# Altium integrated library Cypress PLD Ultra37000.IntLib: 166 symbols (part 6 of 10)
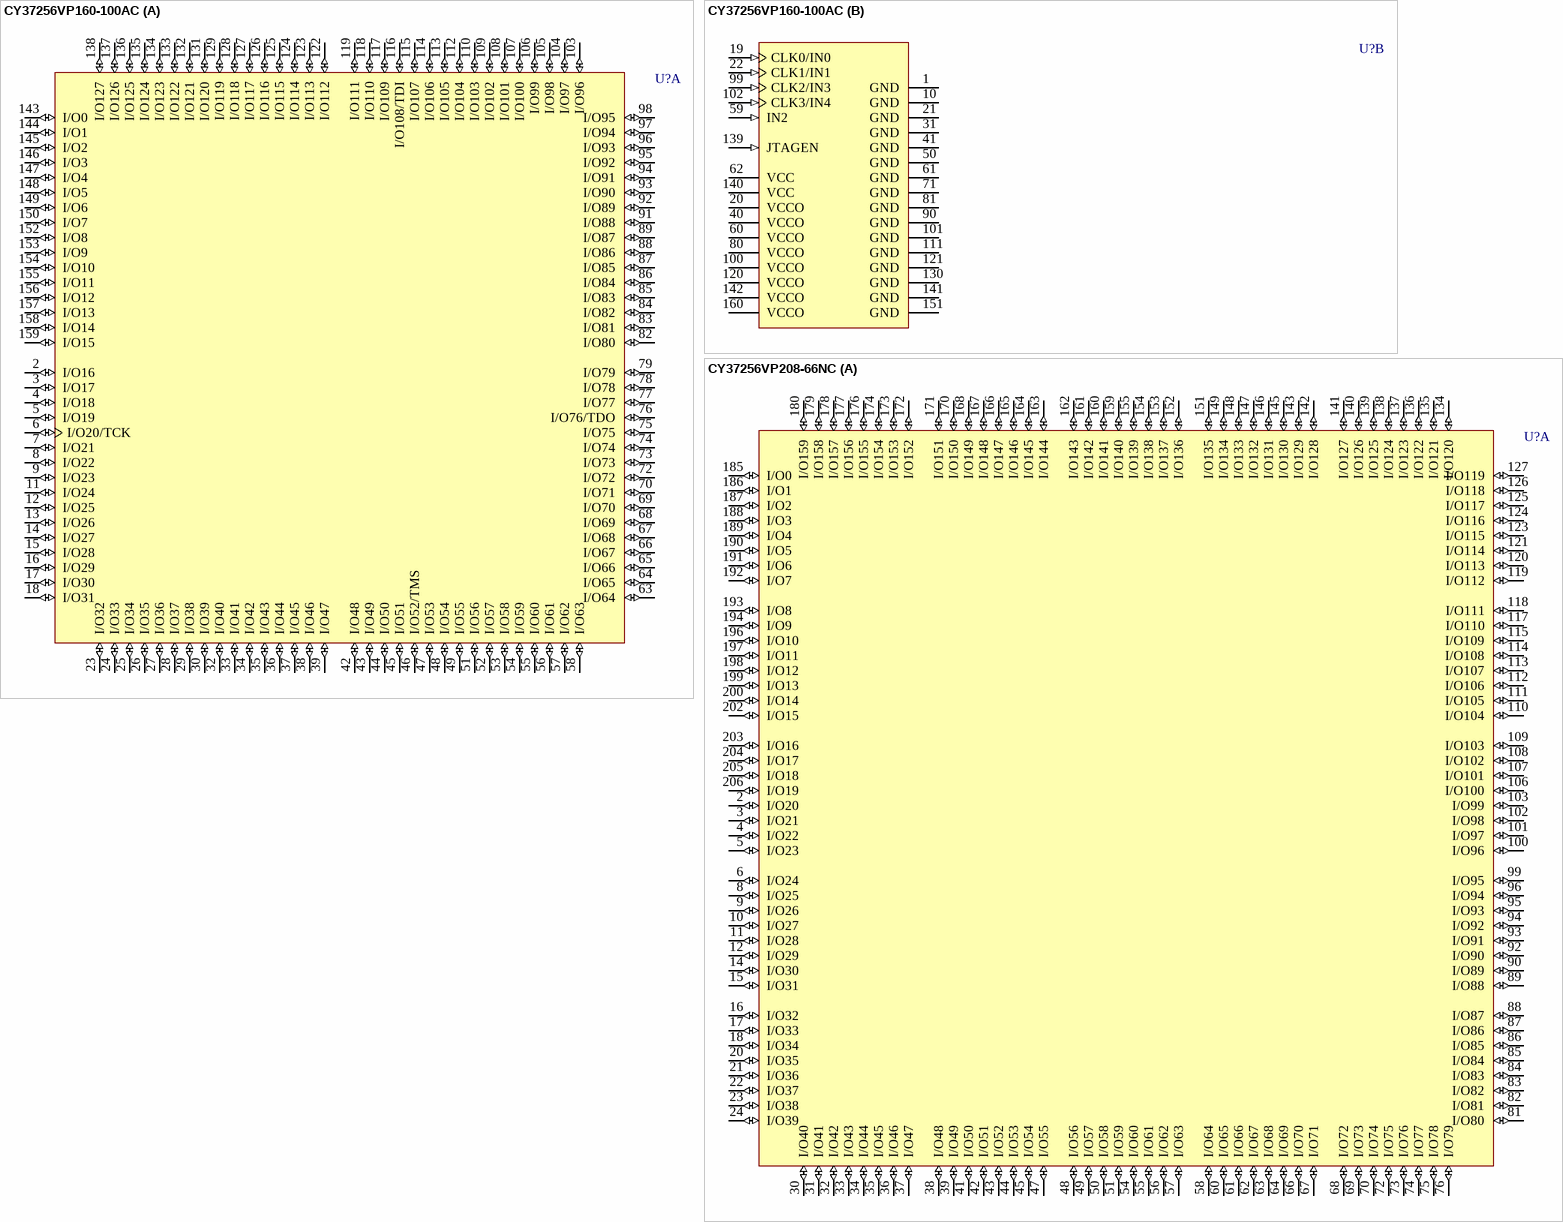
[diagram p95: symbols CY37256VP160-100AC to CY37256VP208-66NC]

## CY37256VP160-100AC
designator U?
Ultra37000 3.3V, ISR High-Performance CPLD
footprint A160_N (Thin QFP, 160-Leads, Body 24x24mm, Pitch 0.5mm, IPC Medium Density)
footprint A160_L (Thin QFP, 160-Leads, Body 24x24mm, Pitch 0.5mm, IPC High Density)
footprint A160_M (Thin QFP, 160-Leads, Body 24x24mm, Pitch 0.5mm, IPC Low Density)
3D model CY37256VP160-A160 (160-Pin Thin Quad Flat Pack 0.5 mm Pitch)
part A pins: 2 I/O16 (io), 3 I/O17 (io), 4 I/O18 (io), 5 I/O19 (io), 6 I/O20/TCK (io), 7 I/O21 (io), 8 I/O22 (io), 9 I/O23 (io), 11 I/O24 (io), 12 I/O25 (io), 13 I/O26 (io), 14 I/O27 (io), 15 I/O28 (io), 16 I/O29 (io), 17 I/O30 (io), 18 I/O31 (io), 23 I/O32 (io), 24 I/O33 (io), 25 I/O34 (io), 26 I/O35 (io), 27 I/O36 (io), 28 I/O37 (io), 29 I/O38 (io), 30 I/O39 (io), 32 I/O40 (io), 33 I/O41 (io), 34 I/O42 (io), 35 I/O43 (io), 36 I/O44 (io), 37 I/O45 (io), 38 I/O46 (io), 39 I/O47 (io), 42 I/O48 (io), 43 I/O49 (io), 44 I/O50 (io), 45 I/O51 (io), 46 I/O52/TMS (io), 47 I/O53 (io), 48 I/O54 (io), 49 I/O55 (io), 51 I/O56 (io), 52 I/O57 (io), 53 I/O58 (io), 54 I/O59 (io), 55 I/O60 (io), 56 I/O61 (io), 57 I/O62 (io), 58 I/O63 (io), 63 I/O64 (io), 64 I/O65 (io), 65 I/O66 (io), 66 I/O67 (io), 67 I/O68 (io), 68 I/O69 (io), 69 I/O70 (io), 70 I/O71 (io), 72 I/O72 (io), 73 I/O73 (io), 74 I/O74 (io), 75 I/O75 (io), 76 I/O76/TDO (io), 77 I/O77 (io), 78 I/O78 (io), 79 I/O79 (io), 82 I/O80 (io), 83 I/O81 (io), 84 I/O82 (io), 85 I/O83 (io), 86 I/O84 (io), 87 I/O85 (io), 88 I/O86 (io), 89 I/O87 (io), 91 I/O88 (io), 92 I/O89 (io), 93 I/O90 (io), 94 I/O91 (io), 95 I/O92 (io), 96 I/O93 (io), 97 I/O94 (io), 98 I/O95 (io), 103 I/O96 (io), 104 I/O97 (io), 105 I/O98 (io), 106 I/O99 (io), 107 I/O100 (io), 108 I/O101 (io), 109 I/O102 (io), 110 I/O103 (io), 112 I/O104 (io), 113 I/O105 (io), 114 I/O106 (io), 115 I/O107 (io), 116 I/O108/TDI (io), 117 I/O109 (io), 118 I/O110 (io), 119 I/O111 (io), 122 I/O112 (io), 123 I/O113 (io), 124 I/O114 (io), 125 I/O115 (io), 126 I/O116 (io), 127 I/O117 (io), 128 I/O118 (io), 129 I/O119 (io), 131 I/O120 (io), 132 I/O121 (io), 133 I/O122 (io), 134 I/O123 (io), 135 I/O124 (io), 136 I/O125 (io), 137 I/O126 (io), 138 I/O127 (io), 143 I/O0 (io), 144 I/O1 (io), 145 I/O2 (io), 146 I/O3 (io), 147 I/O4 (io), 148 I/O5 (io), 149 I/O6 (io), 150 I/O7 (io), 152 I/O8 (io), 153 I/O9 (io), 154 I/O10 (io), 155 I/O11 (io), 156 I/O12 (io), 157 I/O13 (io), 158 I/O14 (io), 159 I/O15 (io)
part B pins: 1 GND (power), 10 GND (power), 19 CLK0/IN0 (in), 20 VCCO (power), 21 GND (power), 22 CLK1/IN1 (in), 31 GND (power), 40 VCCO (power), 41 GND (power), 50 GND (power), 59 IN2 (in), 60 VCCO (power), 61 GND (power), 62 VCC (power), 71 GND (power), 80 VCCO (power), 81 GND (power), 90 GND (power), 99 CLK2/IN3 (in), 100 VCCO (power), 101 GND (power), 102 CLK3/IN4 (in), 111 GND (power), 120 VCCO (power), 121 GND (power), 130 GND (power), 139 JTAGEN (in), 140 VCC (power), 141 GND (power), 142 VCCO (power), 151 GND (power), 160 VCCO (power)

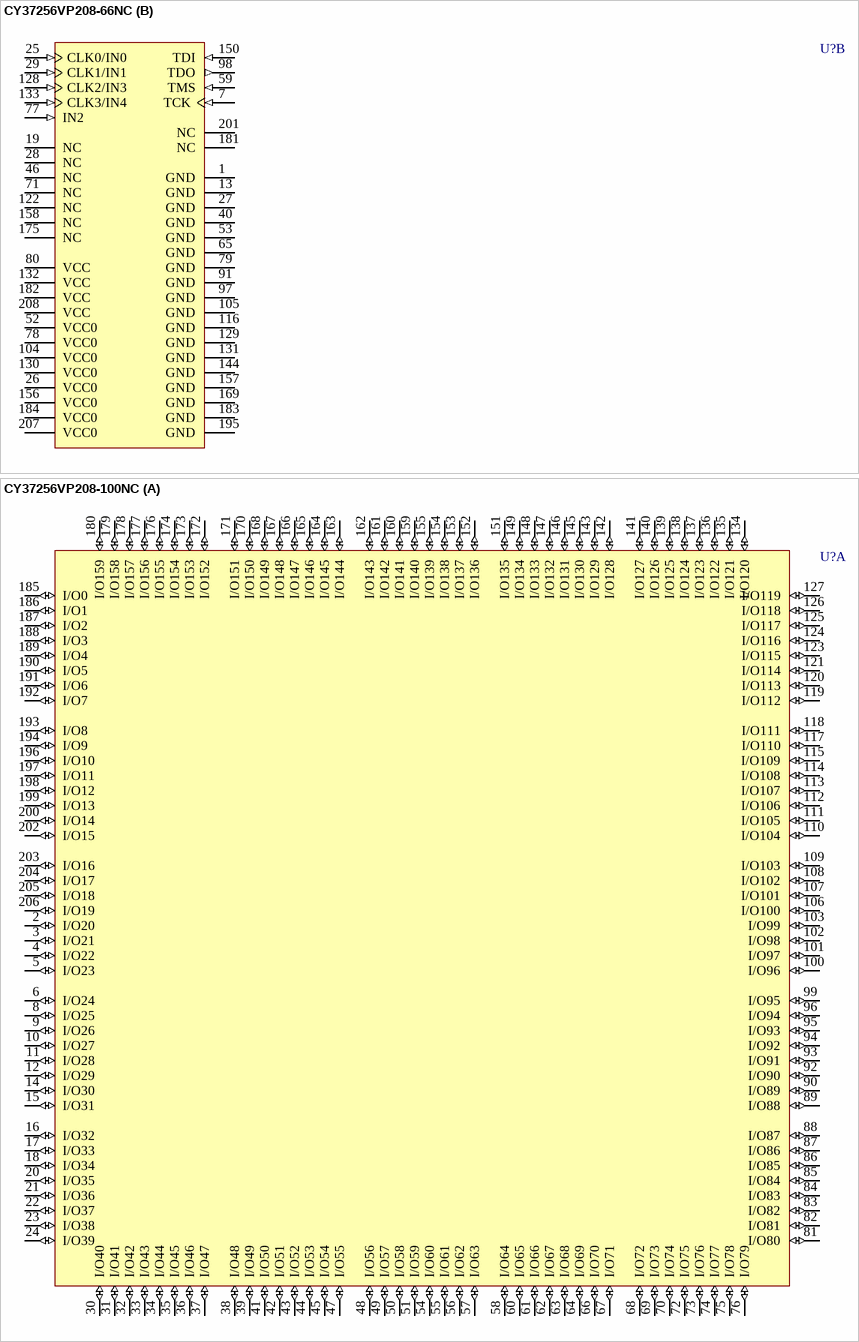
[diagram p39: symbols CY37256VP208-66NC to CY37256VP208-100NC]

## CY37256VP208-66NC
designator U?
Ultra37000 3.3V, ISR High-Performance CPLD
footprint N208_N (Shrink QFP, 208-Leads, Body 28x28mm, Pitch 0.5mm, IPC Medium Density)
footprint N208_L (Shrink QFP, 208-Leads, Body 28x28mm, Pitch 0.5mm, IPC High Density)
footprint N208_M (Shrink QFP, 208-Leads, Body 28x28mm, Pitch 0.5mm, IPC Low Density)
3D model CY37256VP208-N208 (208-Pin Plastic Shrink Quad Flat Pack 0.5 mm Pitch)
part A pins: 2 I/O20 (io), 3 I/O21 (io), 4 I/O22 (io), 5 I/O23 (io), 6 I/O24 (io), 8 I/O25 (io), 9 I/O26 (io), 10 I/O27 (io), 11 I/O28 (io), 12 I/O29 (io), 14 I/O30 (io), 15 I/O31 (io), 16 I/O32 (io), 17 I/O33 (io), 18 I/O34 (io), 20 I/O35 (io), 21 I/O36 (io), 22 I/O37 (io), 23 I/O38 (io), 24 I/O39 (io), 30 I/O40 (io), 31 I/O41 (io), 32 I/O42 (io), 33 I/O43 (io), 34 I/O44 (io), 35 I/O45 (io), 36 I/O46 (io), 37 I/O47 (io), 38 I/O48 (io), 39 I/O49 (io), 41 I/O50 (io), 42 I/O51 (io), 43 I/O52 (io), 44 I/O53 (io), 45 I/O54 (io), 47 I/O55 (io), 48 I/O56 (io), 49 I/O57 (io), 50 I/O58 (io), 51 I/O59 (io), 54 I/O60 (io), 55 I/O61 (io), 56 I/O62 (io), 57 I/O63 (io), 58 I/O64 (io), 60 I/O65 (io), 61 I/O66 (io), 62 I/O67 (io), 63 I/O68 (io), 64 I/O69 (io), 66 I/O70 (io), 67 I/O71 (io), 68 I/O72 (io), 69 I/O73 (io), 70 I/O74 (io), 72 I/O75 (io), 73 I/O76 (io), 74 I/O77 (io), 75 I/O78 (io), 76 I/O79 (io), 81 I/O80 (io), 82 I/O81 (io), 83 I/O82 (io), 84 I/O83 (io), 85 I/O84 (io), 86 I/O85 (io), 87 I/O86 (io), 88 I/O87 (io), 89 I/O88 (io), 90 I/O89 (io), 92 I/O90 (io), 93 I/O91 (io), 94 I/O92 (io), 95 I/O93 (io), 96 I/O94 (io), 99 I/O95 (io), 100 I/O96 (io), 101 I/O97 (io), 102 I/O98 (io), 103 I/O99 (io), 106 I/O100 (io), 107 I/O101 (io), 108 I/O102 (io), 109 I/O103 (io), 110 I/O104 (io), 111 I/O105 (io), 112 I/O106 (io), 113 I/O107 (io), 114 I/O108 (io), 115 I/O109 (io), 117 I/O110 (io), 118 I/O111 (io), 119 I/O112 (io), 120 I/O113 (io), 121 I/O114 (io), 123 I/O115 (io), 124 I/O116 (io), 125 I/O117 (io), 126 I/O118 (io), 127 I/O119 (io), 134 I/O120 (io), 135 I/O121 (io), 136 I/O122 (io), 137 I/O123 (io), 138 I/O124 (io), 139 I/O125 (io), 140 I/O126 (io), 141 I/O127 (io), 142 I/O128 (io), 143 I/O129 (io), 145 I/O130 (io), 146 I/O131 (io), 147 I/O132 (io), 148 I/O133 (io), 149 I/O134 (io), 151 I/O135 (io), 152 I/O136 (io), 153 I/O137 (io), 154 I/O138 (io), 155 I/O139 (io), 159 I/O140 (io), 160 I/O141 (io), 161 I/O142 (io), 162 I/O143 (io), 163 I/O144 (io), 164 I/O145 (io), 165 I/O146 (io), 166 I/O147 (io), 167 I/O148 (io), 168 I/O149 (io), 170 I/O150 (io), 171 I/O151 (io), 172 I/O152 (io), 173 I/O153 (io), 174 I/O154 (io), 176 I/O155 (io), 177 I/O156 (io), 178 I/O157 (io), 179 I/O158 (io), 180 I/O159 (io), 185 I/O0 (io), 186 I/O1 (io), 187 I/O2 (io), 188 I/O3 (io), 189 I/O4 (io), 190 I/O5 (io), 191 I/O6 (io), 192 I/O7 (io), 193 I/O8 (io), 194 I/O9 (io), 196 I/O10 (io), 197 I/O11 (io), 198 I/O12 (io), 199 I/O13 (io), 200 I/O14 (io), 202 I/O15 (io), 203 I/O16 (io), 204 I/O17 (io), 205 I/O18 (io), 206 I/O19 (io)
part B pins: 1 GND (power), 7 TCK (in), 13 GND (power), 19 NC, 25 CLK0/IN0 (in), 26 VCC0 (power), 27 GND (power), 28 NC, 29 CLK1/IN1 (in), 40 GND (power), 46 NC, 52 VCC0 (power), 53 GND (power), 59 TMS (in), 65 GND (power), 71 NC, 77 IN2 (in), 78 VCC0 (power), 79 GND (power), 80 VCC (power), 91 GND (power), 97 GND (power), 98 TDO (out), 104 VCC0 (power), 105 GND (power), 116 GND (power), 122 NC, 128 CLK2/IN3 (in), 129 GND (power), 130 VCC0 (power), 131 GND (power), 132 VCC (power), 133 CLK3/IN4 (in), 144 GND (power), 150 TDI (in), 156 VCC0 (power), 157 GND (power), 158 NC, 169 GND (power), 175 NC, 181 NC, 182 VCC (power), 183 GND (power), 184 VCC0 (power), 195 GND (power), 201 NC, 207 VCC0 (power), 208 VCC (power)

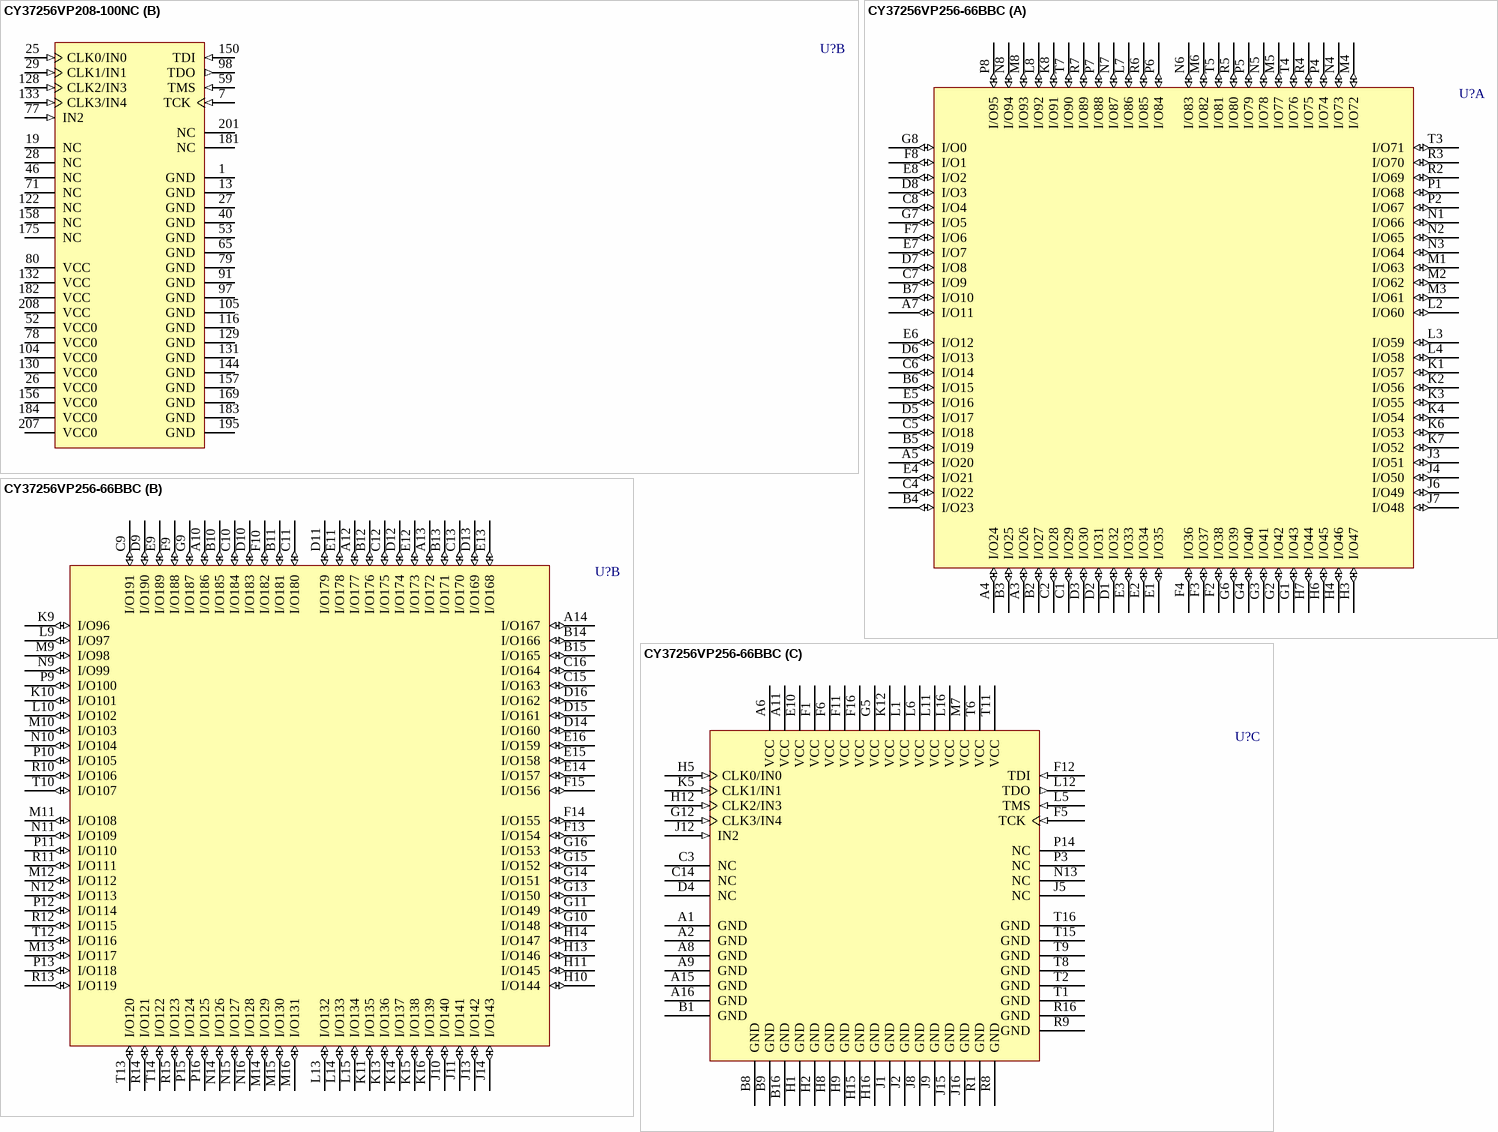
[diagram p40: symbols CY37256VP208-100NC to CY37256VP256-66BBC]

## CY37256VP208-100NC
designator U?
Ultra37000 3.3V, ISR High-Performance CPLD
footprint N208_N (Shrink QFP, 208-Leads, Body 28x28mm, Pitch 0.5mm, IPC Medium Density)
footprint N208_L (Shrink QFP, 208-Leads, Body 28x28mm, Pitch 0.5mm, IPC High Density)
footprint N208_M (Shrink QFP, 208-Leads, Body 28x28mm, Pitch 0.5mm, IPC Low Density)
3D model CY37256VP208-N208 (208-Pin Plastic Shrink Quad Flat Pack 0.5 mm Pitch)
part A pins: 2 I/O20 (io), 3 I/O21 (io), 4 I/O22 (io), 5 I/O23 (io), 6 I/O24 (io), 8 I/O25 (io), 9 I/O26 (io), 10 I/O27 (io), 11 I/O28 (io), 12 I/O29 (io), 14 I/O30 (io), 15 I/O31 (io), 16 I/O32 (io), 17 I/O33 (io), 18 I/O34 (io), 20 I/O35 (io), 21 I/O36 (io), 22 I/O37 (io), 23 I/O38 (io), 24 I/O39 (io), 30 I/O40 (io), 31 I/O41 (io), 32 I/O42 (io), 33 I/O43 (io), 34 I/O44 (io), 35 I/O45 (io), 36 I/O46 (io), 37 I/O47 (io), 38 I/O48 (io), 39 I/O49 (io), 41 I/O50 (io), 42 I/O51 (io), 43 I/O52 (io), 44 I/O53 (io), 45 I/O54 (io), 47 I/O55 (io), 48 I/O56 (io), 49 I/O57 (io), 50 I/O58 (io), 51 I/O59 (io), 54 I/O60 (io), 55 I/O61 (io), 56 I/O62 (io), 57 I/O63 (io), 58 I/O64 (io), 60 I/O65 (io), 61 I/O66 (io), 62 I/O67 (io), 63 I/O68 (io), 64 I/O69 (io), 66 I/O70 (io), 67 I/O71 (io), 68 I/O72 (io), 69 I/O73 (io), 70 I/O74 (io), 72 I/O75 (io), 73 I/O76 (io), 74 I/O77 (io), 75 I/O78 (io), 76 I/O79 (io), 81 I/O80 (io), 82 I/O81 (io), 83 I/O82 (io), 84 I/O83 (io), 85 I/O84 (io), 86 I/O85 (io), 87 I/O86 (io), 88 I/O87 (io), 89 I/O88 (io), 90 I/O89 (io), 92 I/O90 (io), 93 I/O91 (io), 94 I/O92 (io), 95 I/O93 (io), 96 I/O94 (io), 99 I/O95 (io), 100 I/O96 (io), 101 I/O97 (io), 102 I/O98 (io), 103 I/O99 (io), 106 I/O100 (io), 107 I/O101 (io), 108 I/O102 (io), 109 I/O103 (io), 110 I/O104 (io), 111 I/O105 (io), 112 I/O106 (io), 113 I/O107 (io), 114 I/O108 (io), 115 I/O109 (io), 117 I/O110 (io), 118 I/O111 (io), 119 I/O112 (io), 120 I/O113 (io), 121 I/O114 (io), 123 I/O115 (io), 124 I/O116 (io), 125 I/O117 (io), 126 I/O118 (io), 127 I/O119 (io), 134 I/O120 (io), 135 I/O121 (io), 136 I/O122 (io), 137 I/O123 (io), 138 I/O124 (io), 139 I/O125 (io), 140 I/O126 (io), 141 I/O127 (io), 142 I/O128 (io), 143 I/O129 (io), 145 I/O130 (io), 146 I/O131 (io), 147 I/O132 (io), 148 I/O133 (io), 149 I/O134 (io), 151 I/O135 (io), 152 I/O136 (io), 153 I/O137 (io), 154 I/O138 (io), 155 I/O139 (io), 159 I/O140 (io), 160 I/O141 (io), 161 I/O142 (io), 162 I/O143 (io), 163 I/O144 (io), 164 I/O145 (io), 165 I/O146 (io), 166 I/O147 (io), 167 I/O148 (io), 168 I/O149 (io), 170 I/O150 (io), 171 I/O151 (io), 172 I/O152 (io), 173 I/O153 (io), 174 I/O154 (io), 176 I/O155 (io), 177 I/O156 (io), 178 I/O157 (io), 179 I/O158 (io), 180 I/O159 (io), 185 I/O0 (io), 186 I/O1 (io), 187 I/O2 (io), 188 I/O3 (io), 189 I/O4 (io), 190 I/O5 (io), 191 I/O6 (io), 192 I/O7 (io), 193 I/O8 (io), 194 I/O9 (io), 196 I/O10 (io), 197 I/O11 (io), 198 I/O12 (io), 199 I/O13 (io), 200 I/O14 (io), 202 I/O15 (io), 203 I/O16 (io), 204 I/O17 (io), 205 I/O18 (io), 206 I/O19 (io)
part B pins: 1 GND (power), 7 TCK (in), 13 GND (power), 19 NC, 25 CLK0/IN0 (in), 26 VCC0 (power), 27 GND (power), 28 NC, 29 CLK1/IN1 (in), 40 GND (power), 46 NC, 52 VCC0 (power), 53 GND (power), 59 TMS (in), 65 GND (power), 71 NC, 77 IN2 (in), 78 VCC0 (power), 79 GND (power), 80 VCC (power), 91 GND (power), 97 GND (power), 98 TDO (out), 104 VCC0 (power), 105 GND (power), 116 GND (power), 122 NC, 128 CLK2/IN3 (in), 129 GND (power), 130 VCC0 (power), 131 GND (power), 132 VCC (power), 133 CLK3/IN4 (in), 144 GND (power), 150 TDI (in), 156 VCC0 (power), 157 GND (power), 158 NC, 169 GND (power), 175 NC, 181 NC, 182 VCC (power), 183 GND (power), 184 VCC0 (power), 195 GND (power), 201 NC, 207 VCC0 (power), 208 VCC (power)

## CY37256VP256-66BBC
designator U?
Ultra37000 3.3V, ISR High-Performance CPLD
footprint BB256 (BGA, 256-Leads, Body 17x17mm, Pitch 1mm)
3D model CY37256VP256-BB256 (256-Ball Fine Pitch Ball Grid Array 1 mm Pitch (37K & 39K CPLD Devices))
part A pins: A3 I/O26 (io), A4 I/O24 (io), A5 I/O20 (io), A7 I/O11 (io), B2 I/O27 (io), B3 I/O25 (io), B4 I/O23 (io), B5 I/O19 (io), B6 I/O15 (io), B7 I/O10 (io), C1 I/O29 (io), C2 I/O28 (io), C4 I/O22 (io), C5 I/O18 (io), C6 I/O14 (io), C7 I/O9 (io), C8 I/O4 (io), D1 I/O32 (io), D2 I/O31 (io), D3 I/O30 (io), D5 I/O17 (io), D6 I/O13 (io), D7 I/O8 (io), D8 I/O3 (io), E1 I/O35 (io), E2 I/O34 (io), E3 I/O33 (io), E4 I/O21 (io), E5 I/O16 (io), E6 I/O12 (io), E7 I/O7 (io), E8 I/O2 (io), F2 I/O38 (io), F3 I/O37 (io), F4 I/O36 (io), F7 I/O6 (io), F8 I/O1 (io), G1 I/O43 (io), G2 I/O42 (io), G3 I/O41 (io), G4 I/O40 (io), G6 I/O39 (io), G7 I/O5 (io), G8 I/O0 (io), H3 I/O47 (io), H4 I/O46 (io), H6 I/O45 (io), H7 I/O44 (io), J3 I/O51 (io), J4 I/O50 (io), J6 I/O49 (io), J7 I/O48 (io), K1 I/O57 (io), K2 I/O56 (io), K3 I/O55 (io), K4 I/O54 (io), K6 I/O53 (io), K7 I/O52 (io), K8 I/O91 (io), L2 I/O60 (io), L3 I/O59 (io), L4 I/O58 (io), L7 I/O86 (io), L8 I/O92 (io), M1 I/O63 (io), M2 I/O62 (io), M3 I/O61 (io), M4 I/O72 (io), M5 I/O77 (io), M6 I/O82 (io), M8 I/O93 (io), N1 I/O66 (io), N2 I/O65 (io), N3 I/O64 (io), N4 I/O73 (io), N5 I/O78 (io), N6 I/O83 (io), N7 I/O87 (io), N8 I/O94 (io), P1 I/O68 (io), P2 I/O67 (io), P4 I/O74 (io), P5 I/O79 (io), P6 I/O84 (io), P7 I/O88 (io), P8 I/O95 (io), R2 I/O69 (io), R3 I/O70 (io), R4 I/O75 (io), R5 I/O80 (io), R6 I/O85 (io), R7 I/O89 (io), T3 I/O71 (io), T4 I/O76 (io), T5 I/O81 (io), T7 I/O90 (io)
part B pins: A10 I/O186 (io), A12 I/O177 (io), A13 I/O172 (io), A14 I/O167 (io), B10 I/O185 (io), B11 I/O181 (io), B12 I/O176 (io), B13 I/O171 (io), B14 I/O166 (io), B15 I/O165 (io), C9 I/O191 (io), C10 I/O184 (io), C11 I/O180 (io), C12 I/O175 (io), C13 I/O170 (io), C15 I/O163 (io), C16 I/O164 (io), D9 I/O190 (io), D10 I/O183 (io), D11 I/O179 (io), D12 I/O174 (io), D13 I/O169 (io), D14 I/O160 (io), D15 I/O161 (io), D16 I/O162 (io), E9 I/O189 (io), E11 I/O178 (io), E12 I/O173 (io), E13 I/O168 (io), E14 I/O157 (io), E15 I/O158 (io), E16 I/O159 (io), F9 I/O188 (io), F10 I/O182 (io), F13 I/O154 (io), F14 I/O155 (io), F15 I/O156 (io), G9 I/O187 (io), G10 I/O148 (io), G11 I/O149 (io), G13 I/O150 (io), G14 I/O151 (io), G15 I/O152 (io), G16 I/O153 (io), H10 I/O144 (io), H11 I/O145 (io), H13 I/O146 (io), H14 I/O147 (io), J10 I/O140 (io), J11 I/O141 (io), J13 I/O142 (io), J14 I/O143 (io), K9 I/O96 (io), K10 I/O101 (io), K11 I/O135 (io), K13 I/O136 (io), K14 I/O137 (io), K15 I/O138 (io), K16 I/O139 (io), L9 I/O97 (io), L10 I/O102 (io), L13 I/O132 (io), L14 I/O133 (io), L15 I/O134 (io), M9 I/O98 (io), M10 I/O103 (io), M11 I/O108 (io), M12 I/O112 (io), M13 I/O117 (io), M14 I/O129 (io), M15 I/O130 (io), M16 I/O131 (io), N9 I/O99 (io), N10 I/O104 (io), N11 I/O109 (io), N12 I/O113 (io), N14 I/O126 (io), N15 I/O127 (io), N16 I/O128 (io), P9 I/O100 (io), P10 I/O105 (io), P11 I/O110 (io), P12 I/O114 (io), P13 I/O118 (io), P15 I/O124 (io), P16 I/O125 (io), R10 I/O106 (io), R11 I/O111 (io), R12 I/O115 (io), R13 I/O119 (io), R14 I/O121 (io), R15 I/O123 (io), T10 I/O107 (io), T12 I/O116 (io), T13 I/O120 (io), T14 I/O122 (io)
part C pins: A1 GND (power), A2 GND (power), A6 VCC (power), A8 GND (power), A9 GND (power), A11 VCC (power), A15 GND (power), A16 GND (power), B1 GND (power), B8 GND (power), B9 GND (power), B16 GND (power), C3 NC, C14 NC, D4 NC, E10 VCC (power), F1 VCC (power), F5 TCK (in), F6 VCC (power), F11 VCC (power), F12 TDI (in), F16 VCC (power), G5 VCC (power), G12 CLK3/IN4 (in), H1 GND (power), H2 GND (power), H5 CLK0/IN0 (in), H8 GND (power), H9 GND (power), H12 CLK2/IN3 (in), H15 GND (power), H16 GND (power), J1 GND (power), J2 GND (power), J5 NC, J8 GND (power), J9 GND (power), J12 IN2 (in), J15 GND (power), J16 GND (power), K5 CLK1/IN1 (in), K12 VCC (power), L1 VCC (power), L5 TMS (in), L6 VCC (power), L11 VCC (power), L12 TDO (out), L16 VCC (power), M7 VCC (power), N13 NC, P3 NC, P14 NC, R1 GND (power), R8 GND (power), R9 GND (power), R16 GND (power), T1 GND (power), T2 GND (power), T6 VCC (power), T8 GND (power), T9 GND (power), T11 VCC (power), T15 GND (power), T16 GND (power)

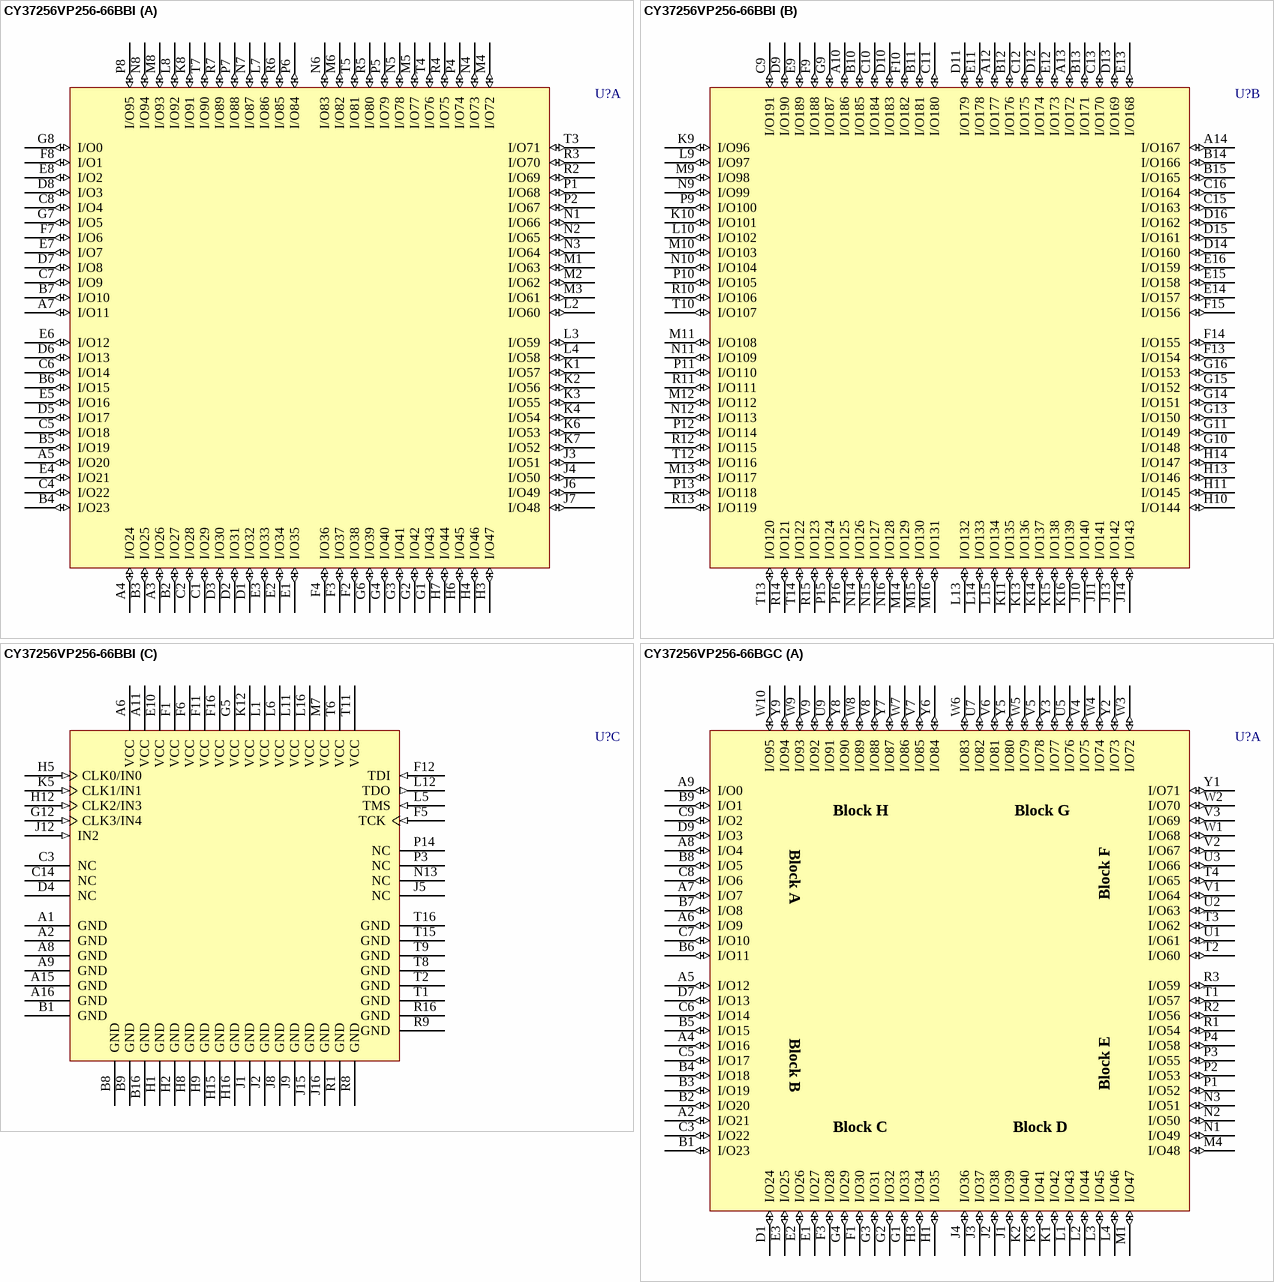
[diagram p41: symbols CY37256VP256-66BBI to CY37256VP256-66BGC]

## CY37256VP256-66BBI
designator U?
Ultra37000 3.3V, ISR High-Performance CPLD
footprint BB256 (BGA, 256-Leads, Body 17x17mm, Pitch 1mm)
3D model CY37256VP256-BB256 (256-Ball Fine Pitch Ball Grid Array 1 mm Pitch (37K & 39K CPLD Devices))
part A pins: A3 I/O26 (io), A4 I/O24 (io), A5 I/O20 (io), A7 I/O11 (io), B2 I/O27 (io), B3 I/O25 (io), B4 I/O23 (io), B5 I/O19 (io), B6 I/O15 (io), B7 I/O10 (io), C1 I/O29 (io), C2 I/O28 (io), C4 I/O22 (io), C5 I/O18 (io), C6 I/O14 (io), C7 I/O9 (io), C8 I/O4 (io), D1 I/O32 (io), D2 I/O31 (io), D3 I/O30 (io), D5 I/O17 (io), D6 I/O13 (io), D7 I/O8 (io), D8 I/O3 (io), E1 I/O35 (io), E2 I/O34 (io), E3 I/O33 (io), E4 I/O21 (io), E5 I/O16 (io), E6 I/O12 (io), E7 I/O7 (io), E8 I/O2 (io), F2 I/O38 (io), F3 I/O37 (io), F4 I/O36 (io), F7 I/O6 (io), F8 I/O1 (io), G1 I/O43 (io), G2 I/O42 (io), G3 I/O41 (io), G4 I/O40 (io), G6 I/O39 (io), G7 I/O5 (io), G8 I/O0 (io), H3 I/O47 (io), H4 I/O46 (io), H6 I/O45 (io), H7 I/O44 (io), J3 I/O51 (io), J4 I/O50 (io), J6 I/O49 (io), J7 I/O48 (io), K1 I/O57 (io), K2 I/O56 (io), K3 I/O55 (io), K4 I/O54 (io), K6 I/O53 (io), K7 I/O52 (io), K8 I/O91 (io), L2 I/O60 (io), L3 I/O59 (io), L4 I/O58 (io), L7 I/O86 (io), L8 I/O92 (io), M1 I/O63 (io), M2 I/O62 (io), M3 I/O61 (io), M4 I/O72 (io), M5 I/O77 (io), M6 I/O82 (io), M8 I/O93 (io), N1 I/O66 (io), N2 I/O65 (io), N3 I/O64 (io), N4 I/O73 (io), N5 I/O78 (io), N6 I/O83 (io), N7 I/O87 (io), N8 I/O94 (io), P1 I/O68 (io), P2 I/O67 (io), P4 I/O74 (io), P5 I/O79 (io), P6 I/O84 (io), P7 I/O88 (io), P8 I/O95 (io), R2 I/O69 (io), R3 I/O70 (io), R4 I/O75 (io), R5 I/O80 (io), R6 I/O85 (io), R7 I/O89 (io), T3 I/O71 (io), T4 I/O76 (io), T5 I/O81 (io), T7 I/O90 (io)
part B pins: A10 I/O186 (io), A12 I/O177 (io), A13 I/O172 (io), A14 I/O167 (io), B10 I/O185 (io), B11 I/O181 (io), B12 I/O176 (io), B13 I/O171 (io), B14 I/O166 (io), B15 I/O165 (io), C9 I/O191 (io), C10 I/O184 (io), C11 I/O180 (io), C12 I/O175 (io), C13 I/O170 (io), C15 I/O163 (io), C16 I/O164 (io), D9 I/O190 (io), D10 I/O183 (io), D11 I/O179 (io), D12 I/O174 (io), D13 I/O169 (io), D14 I/O160 (io), D15 I/O161 (io), D16 I/O162 (io), E9 I/O189 (io), E11 I/O178 (io), E12 I/O173 (io), E13 I/O168 (io), E14 I/O157 (io), E15 I/O158 (io), E16 I/O159 (io), F9 I/O188 (io), F10 I/O182 (io), F13 I/O154 (io), F14 I/O155 (io), F15 I/O156 (io), G9 I/O187 (io), G10 I/O148 (io), G11 I/O149 (io), G13 I/O150 (io), G14 I/O151 (io), G15 I/O152 (io), G16 I/O153 (io), H10 I/O144 (io), H11 I/O145 (io), H13 I/O146 (io), H14 I/O147 (io), J10 I/O140 (io), J11 I/O141 (io), J13 I/O142 (io), J14 I/O143 (io), K9 I/O96 (io), K10 I/O101 (io), K11 I/O135 (io), K13 I/O136 (io), K14 I/O137 (io), K15 I/O138 (io), K16 I/O139 (io), L9 I/O97 (io), L10 I/O102 (io), L13 I/O132 (io), L14 I/O133 (io), L15 I/O134 (io), M9 I/O98 (io), M10 I/O103 (io), M11 I/O108 (io), M12 I/O112 (io), M13 I/O117 (io), M14 I/O129 (io), M15 I/O130 (io), M16 I/O131 (io), N9 I/O99 (io), N10 I/O104 (io), N11 I/O109 (io), N12 I/O113 (io), N14 I/O126 (io), N15 I/O127 (io), N16 I/O128 (io), P9 I/O100 (io), P10 I/O105 (io), P11 I/O110 (io), P12 I/O114 (io), P13 I/O118 (io), P15 I/O124 (io), P16 I/O125 (io), R10 I/O106 (io), R11 I/O111 (io), R12 I/O115 (io), R13 I/O119 (io), R14 I/O121 (io), R15 I/O123 (io), T10 I/O107 (io), T12 I/O116 (io), T13 I/O120 (io), T14 I/O122 (io)
part C pins: A1 GND (power), A2 GND (power), A6 VCC (power), A8 GND (power), A9 GND (power), A11 VCC (power), A15 GND (power), A16 GND (power), B1 GND (power), B8 GND (power), B9 GND (power), B16 GND (power), C3 NC, C14 NC, D4 NC, E10 VCC (power), F1 VCC (power), F5 TCK (in), F6 VCC (power), F11 VCC (power), F12 TDI (in), F16 VCC (power), G5 VCC (power), G12 CLK3/IN4 (in), H1 GND (power), H2 GND (power), H5 CLK0/IN0 (in), H8 GND (power), H9 GND (power), H12 CLK2/IN3 (in), H15 GND (power), H16 GND (power), J1 GND (power), J2 GND (power), J5 NC, J8 GND (power), J9 GND (power), J12 IN2 (in), J15 GND (power), J16 GND (power), K5 CLK1/IN1 (in), K12 VCC (power), L1 VCC (power), L5 TMS (in), L6 VCC (power), L11 VCC (power), L12 TDO (out), L16 VCC (power), M7 VCC (power), N13 NC, P3 NC, P14 NC, R1 GND (power), R8 GND (power), R9 GND (power), R16 GND (power), T1 GND (power), T2 GND (power), T6 VCC (power), T8 GND (power), T9 GND (power), T11 VCC (power), T15 GND (power), T16 GND (power)

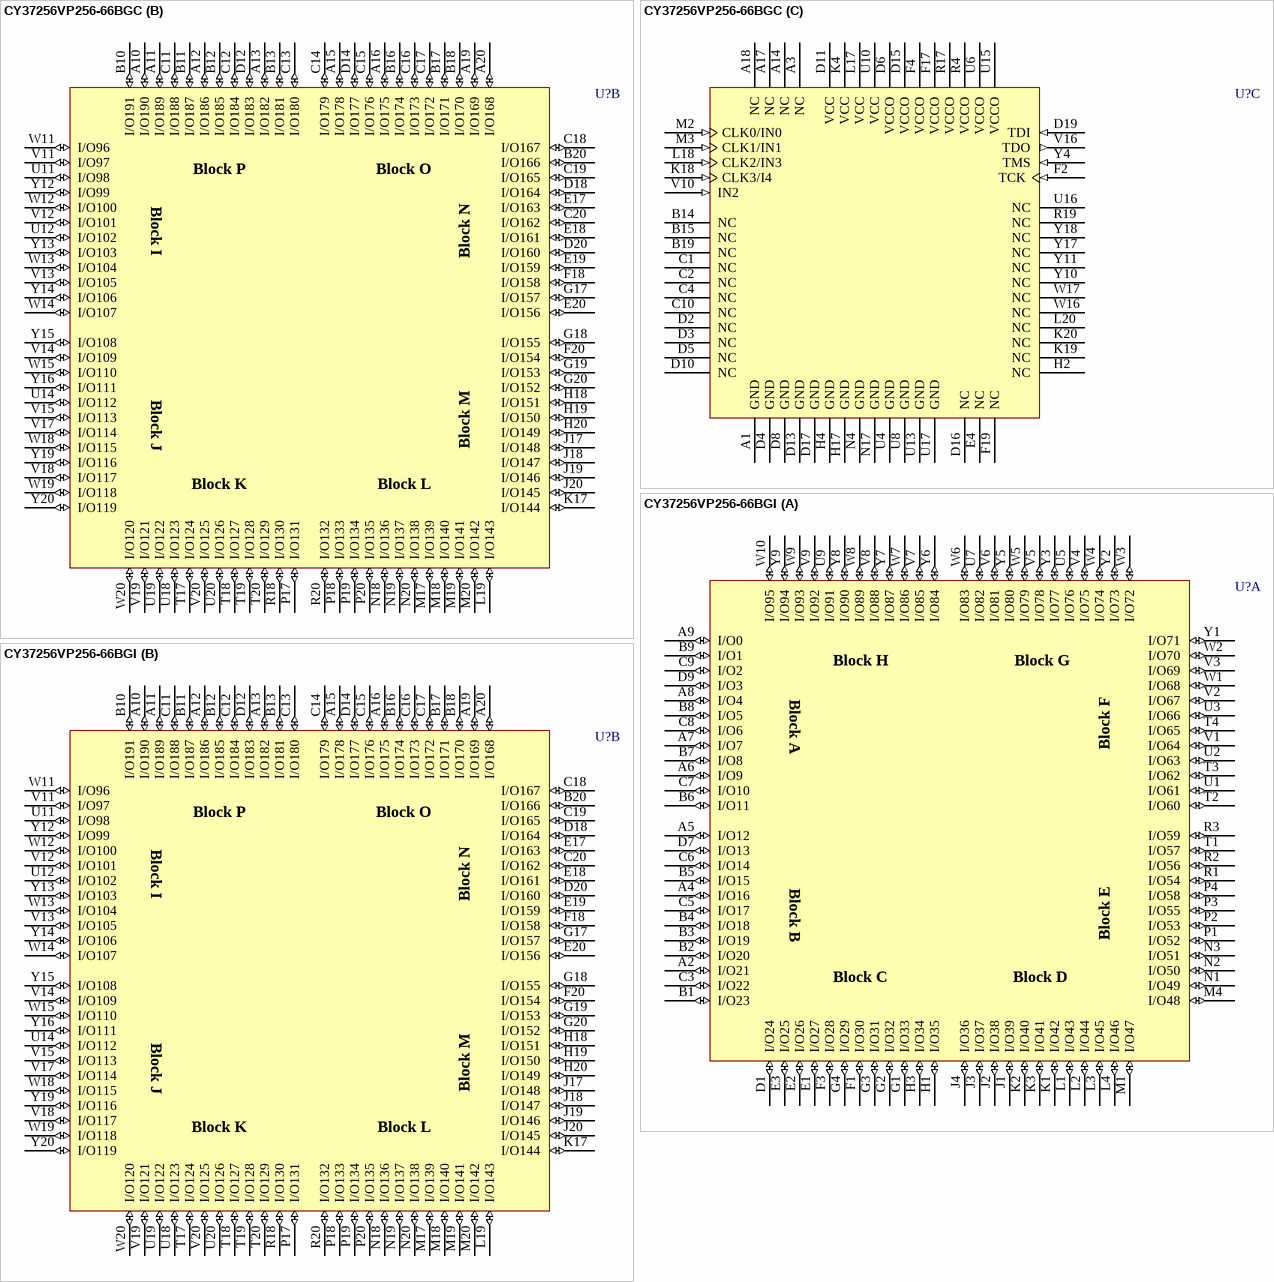
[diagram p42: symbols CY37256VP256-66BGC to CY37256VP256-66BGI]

## CY37256VP256-66BGC
designator U?
Ultra37000 3.3V, ISR High-Performance CPLD
footprint BG256 (BGA, 292-Leads, Body 27x27mm, Pitch 1.27mm)
3D model CY37256VP256-BG256 (292-Ball Ball Grid Array 1.27 mm Pitch)
part A pins: A2 I/O21 (io), A4 I/O16 (io), A5 I/O12 (io), A6 I/O9 (io), A7 I/O7 (io), A8 I/O4 (io), A9 I/O0 (io), B1 I/O23 (io), B2 I/O20 (io), B3 I/O19 (io), B4 I/O18 (io), B5 I/O15 (io), B6 I/O11 (io), B7 I/O8 (io), B8 I/O5 (io), B9 I/O1 (io), C3 I/O22 (io), C5 I/O17 (io), C6 I/O14 (io), C7 I/O10 (io), C8 I/O6 (io), C9 I/O2 (io), D1 I/O24 (io), D7 I/O13 (io), D9 I/O3 (io), E1 I/O27 (io), E2 I/O26 (io), E3 I/O25 (io), F1 I/O30 (io), F3 I/O28 (io), G1 I/O33 (io), G2 I/O32 (io), G3 I/O31 (io), G4 I/O29 (io), H1 I/O35 (io), H3 I/O34 (io), J1 I/O39 (io), J2 I/O38 (io), J3 I/O37 (io), J4 I/O36 (io), K1 I/O42 (io), K2 I/O40 (io), K3 I/O41 (io), L1 I/O43 (io), L2 I/O44 (io), L3 I/O45 (io), L4 I/O46 (io), M1 I/O47 (io), M4 I/O48 (io), N1 I/O49 (io), N2 I/O50 (io), N3 I/O51 (io), P1 I/O52 (io), P2 I/O53 (io), P3 I/O55 (io), P4 I/O58 (io), R1 I/O54 (io), R2 I/O56 (io), R3 I/O59 (io), T1 I/O57 (io), T2 I/O60 (io), T3 I/O62 (io), T4 I/O65 (io), U1 I/O61 (io), U2 I/O63 (io), U3 I/O66 (io), U5 I/O76 (io), U7 I/O82 (io), U9 I/O91 (io), V1 I/O64 (io), V2 I/O67 (io), V3 I/O69 (io), V4 I/O75 (io), V5 I/O78 (io), V6 I/O81 (io), V7 I/O85 (io), V8 I/O88 (io), V9 I/O92 (io), W1 I/O68 (io), W2 I/O70 (io), W3 I/O72 (io), W4 I/O74 (io), W5 I/O79 (io), W6 I/O83 (io), W7 I/O86 (io), W8 I/O89 (io), W9 I/O93 (io), W10 I/O95 (io), Y1 I/O71 (io), Y2 I/O73 (io), Y3 I/O77 (io), Y5 I/O80 (io), Y6 I/O84 (io), Y7 I/O87 (io), Y8 I/O90 (io), Y9 I/O94 (io)
part B pins: A10 I/O190 (io), A11 I/O189 (io), A12 I/O186 (io), A13 I/O182 (io), A15 I/O178 (io), A16 I/O175 (io), A19 I/O169 (io), A20 I/O168 (io), B10 I/O191 (io), B11 I/O187 (io), B12 I/O185 (io), B13 I/O181 (io), B16 I/O174 (io), B17 I/O171 (io), B18 I/O170 (io), B20 I/O166 (io), C11 I/O188 (io), C12 I/O184 (io), C13 I/O180 (io), C14 I/O179 (io), C15 I/O176 (io), C16 I/O173 (io), C17 I/O172 (io), C18 I/O167 (io), C19 I/O165 (io), C20 I/O162 (io), D12 I/O183 (io), D14 I/O177 (io), D18 I/O164 (io), D20 I/O160 (io), E17 I/O163 (io), E18 I/O161 (io), E19 I/O159 (io), E20 I/O156 (io), F18 I/O158 (io), F20 I/O154 (io), G17 I/O157 (io), G18 I/O155 (io), G19 I/O153 (io), G20 I/O152 (io), H18 I/O151 (io), H19 I/O150 (io), H20 I/O149 (io), J17 I/O148 (io), J18 I/O147 (io), J19 I/O146 (io), J20 I/O145 (io), K17 I/O144 (io), L19 I/O143 (io), M17 I/O139 (io), M18 I/O140 (io), M19 I/O141 (io), M20 I/O142 (io), N18 I/O136 (io), N19 I/O137 (io), N20 I/O138 (io), P17 I/O131 (io), P18 I/O133 (io), P19 I/O134 (io), P20 I/O135 (io), R18 I/O130 (io), R20 I/O132 (io), T17 I/O124 (io), T18 I/O127 (io), T19 I/O128 (io), T20 I/O129 (io), U11 I/O98 (io), U12 I/O102 (io), U14 I/O112 (io), U18 I/O123 (io), U19 I/O122 (io), U20 I/O126 (io), V11 I/O97 (io), V12 I/O101 (io), V13 I/O105 (io), V14 I/O109 (io), V15 I/O113 (io), V17 I/O114 (io), V18 I/O117 (io), V19 I/O121 (io), V20 I/O125 (io), W11 I/O96 (io), W12 I/O100 (io), W13 I/O104 (io), W14 I/O107 (io), W15 I/O110 (io), W18 I/O115 (io), W19 I/O118 (io), W20 I/O120 (io), Y12 I/O99 (io), Y13 I/O103 (io), Y14 I/O106 (io), Y15 I/O108 (io), Y16 I/O111 (io), Y19 I/O116 (io), Y20 I/O119 (io)
part C pins: A1 GND (power), A3 NC, A14 NC, A17 NC, A18 NC, B14 NC, B15 NC, B19 NC, C1 NC, C2 NC, C4 NC, C10 NC, D2 NC, D3 NC, D4 GND (power), D5 NC, D6 VCCO (power), D8 GND (power), D10 NC, D11 VCC (power), D13 GND (power), D15 VCCO (power), D16 NC, D17 GND (power), D19 TDI (in), E4 NC, F2 TCK (in), F4 VCCO (power), F17 VCCO (power), F19 NC, H2 NC, H4 GND (power), H17 GND (power), K4 VCC (power), K18 CLK3/I4 (in), K19 NC, K20 NC, L17 VCC (power), L18 CLK2/IN3 (in), L20 NC, M2 CLK0/IN0 (in), M3 CLK1/IN1 (in), N4 GND (power), N17 GND (power), R4 VCCO (power), R17 VCCO (power), R19 NC, U4 GND (power), U6 VCCO (power), U8 GND (power), U10 VCC (power), U13 GND (power), U15 VCCO (power), U16 NC, U17 GND (power), V10 IN2 (in), V16 TDO (out), W16 NC, W17 NC, Y4 TMS (in), Y10 NC, Y11 NC, Y17 NC, Y18 NC

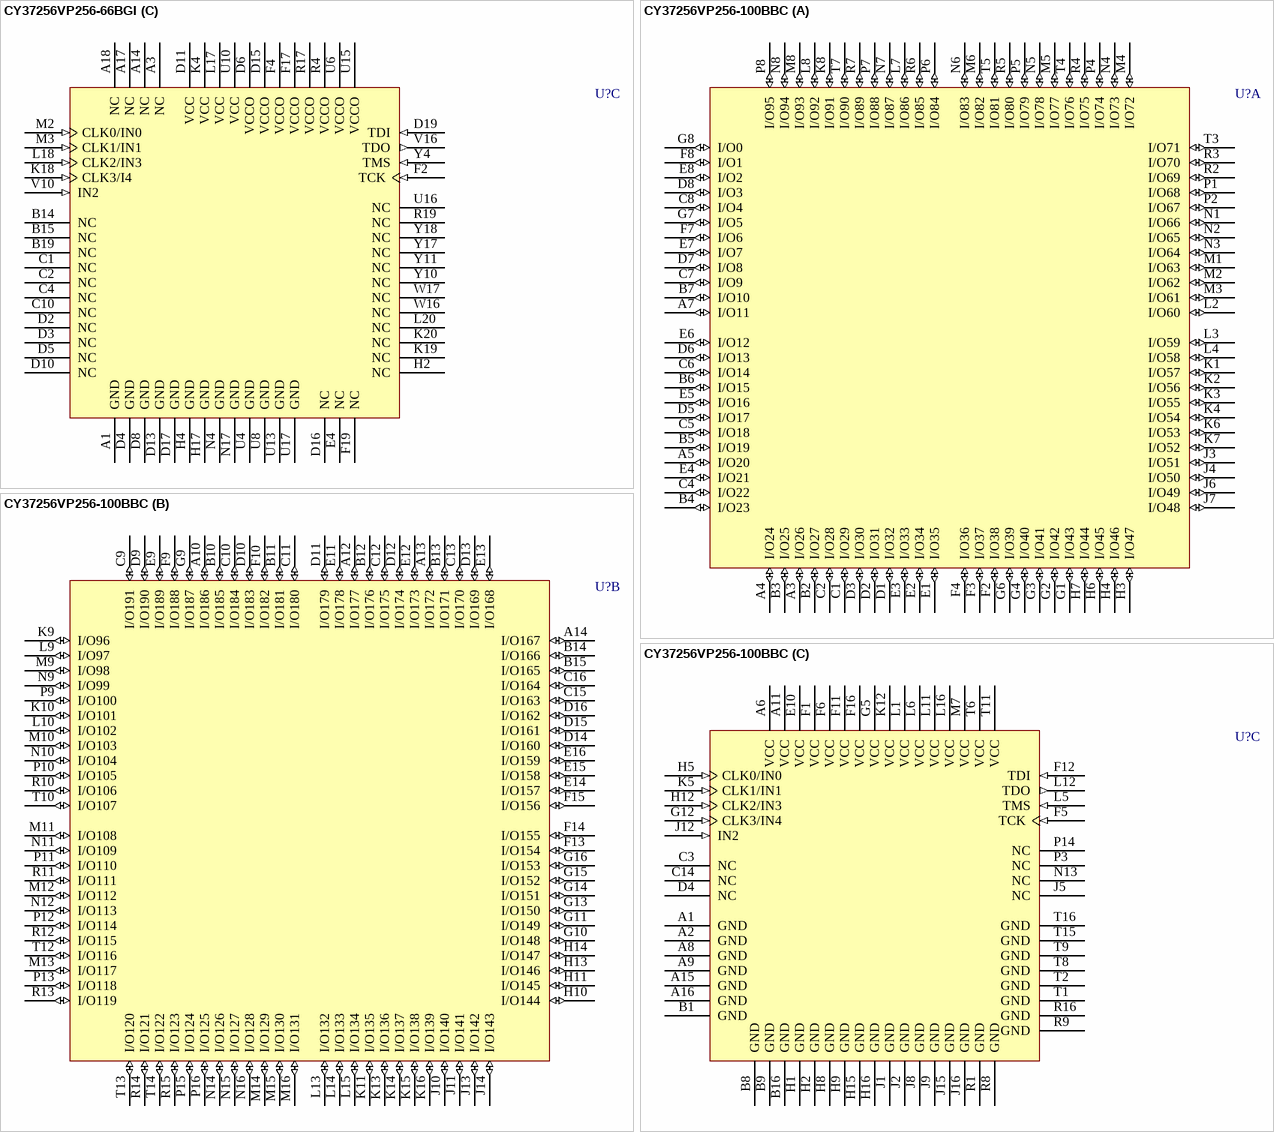
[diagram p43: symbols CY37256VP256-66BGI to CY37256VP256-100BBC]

## CY37256VP256-66BGI
designator U?
Ultra37000 3.3V, ISR High-Performance CPLD
footprint BG256 (BGA, 292-Leads, Body 27x27mm, Pitch 1.27mm)
3D model CY37256VP256-BG256 (292-Ball Ball Grid Array 1.27 mm Pitch)
part A pins: A2 I/O21 (io), A4 I/O16 (io), A5 I/O12 (io), A6 I/O9 (io), A7 I/O7 (io), A8 I/O4 (io), A9 I/O0 (io), B1 I/O23 (io), B2 I/O20 (io), B3 I/O19 (io), B4 I/O18 (io), B5 I/O15 (io), B6 I/O11 (io), B7 I/O8 (io), B8 I/O5 (io), B9 I/O1 (io), C3 I/O22 (io), C5 I/O17 (io), C6 I/O14 (io), C7 I/O10 (io), C8 I/O6 (io), C9 I/O2 (io), D1 I/O24 (io), D7 I/O13 (io), D9 I/O3 (io), E1 I/O27 (io), E2 I/O26 (io), E3 I/O25 (io), F1 I/O30 (io), F3 I/O28 (io), G1 I/O33 (io), G2 I/O32 (io), G3 I/O31 (io), G4 I/O29 (io), H1 I/O35 (io), H3 I/O34 (io), J1 I/O39 (io), J2 I/O38 (io), J3 I/O37 (io), J4 I/O36 (io), K1 I/O42 (io), K2 I/O40 (io), K3 I/O41 (io), L1 I/O43 (io), L2 I/O44 (io), L3 I/O45 (io), L4 I/O46 (io), M1 I/O47 (io), M4 I/O48 (io), N1 I/O49 (io), N2 I/O50 (io), N3 I/O51 (io), P1 I/O52 (io), P2 I/O53 (io), P3 I/O55 (io), P4 I/O58 (io), R1 I/O54 (io), R2 I/O56 (io), R3 I/O59 (io), T1 I/O57 (io), T2 I/O60 (io), T3 I/O62 (io), T4 I/O65 (io), U1 I/O61 (io), U2 I/O63 (io), U3 I/O66 (io), U5 I/O76 (io), U7 I/O82 (io), U9 I/O91 (io), V1 I/O64 (io), V2 I/O67 (io), V3 I/O69 (io), V4 I/O75 (io), V5 I/O78 (io), V6 I/O81 (io), V7 I/O85 (io), V8 I/O88 (io), V9 I/O92 (io), W1 I/O68 (io), W2 I/O70 (io), W3 I/O72 (io), W4 I/O74 (io), W5 I/O79 (io), W6 I/O83 (io), W7 I/O86 (io), W8 I/O89 (io), W9 I/O93 (io), W10 I/O95 (io), Y1 I/O71 (io), Y2 I/O73 (io), Y3 I/O77 (io), Y5 I/O80 (io), Y6 I/O84 (io), Y7 I/O87 (io), Y8 I/O90 (io), Y9 I/O94 (io)
part B pins: A10 I/O190 (io), A11 I/O189 (io), A12 I/O186 (io), A13 I/O182 (io), A15 I/O178 (io), A16 I/O175 (io), A19 I/O169 (io), A20 I/O168 (io), B10 I/O191 (io), B11 I/O187 (io), B12 I/O185 (io), B13 I/O181 (io), B16 I/O174 (io), B17 I/O171 (io), B18 I/O170 (io), B20 I/O166 (io), C11 I/O188 (io), C12 I/O184 (io), C13 I/O180 (io), C14 I/O179 (io), C15 I/O176 (io), C16 I/O173 (io), C17 I/O172 (io), C18 I/O167 (io), C19 I/O165 (io), C20 I/O162 (io), D12 I/O183 (io), D14 I/O177 (io), D18 I/O164 (io), D20 I/O160 (io), E17 I/O163 (io), E18 I/O161 (io), E19 I/O159 (io), E20 I/O156 (io), F18 I/O158 (io), F20 I/O154 (io), G17 I/O157 (io), G18 I/O155 (io), G19 I/O153 (io), G20 I/O152 (io), H18 I/O151 (io), H19 I/O150 (io), H20 I/O149 (io), J17 I/O148 (io), J18 I/O147 (io), J19 I/O146 (io), J20 I/O145 (io), K17 I/O144 (io), L19 I/O143 (io), M17 I/O139 (io), M18 I/O140 (io), M19 I/O141 (io), M20 I/O142 (io), N18 I/O136 (io), N19 I/O137 (io), N20 I/O138 (io), P17 I/O131 (io), P18 I/O133 (io), P19 I/O134 (io), P20 I/O135 (io), R18 I/O130 (io), R20 I/O132 (io), T17 I/O124 (io), T18 I/O127 (io), T19 I/O128 (io), T20 I/O129 (io), U11 I/O98 (io), U12 I/O102 (io), U14 I/O112 (io), U18 I/O123 (io), U19 I/O122 (io), U20 I/O126 (io), V11 I/O97 (io), V12 I/O101 (io), V13 I/O105 (io), V14 I/O109 (io), V15 I/O113 (io), V17 I/O114 (io), V18 I/O117 (io), V19 I/O121 (io), V20 I/O125 (io), W11 I/O96 (io), W12 I/O100 (io), W13 I/O104 (io), W14 I/O107 (io), W15 I/O110 (io), W18 I/O115 (io), W19 I/O118 (io), W20 I/O120 (io), Y12 I/O99 (io), Y13 I/O103 (io), Y14 I/O106 (io), Y15 I/O108 (io), Y16 I/O111 (io), Y19 I/O116 (io), Y20 I/O119 (io)
part C pins: A1 GND (power), A3 NC, A14 NC, A17 NC, A18 NC, B14 NC, B15 NC, B19 NC, C1 NC, C2 NC, C4 NC, C10 NC, D2 NC, D3 NC, D4 GND (power), D5 NC, D6 VCCO (power), D8 GND (power), D10 NC, D11 VCC (power), D13 GND (power), D15 VCCO (power), D16 NC, D17 GND (power), D19 TDI (in), E4 NC, F2 TCK (in), F4 VCCO (power), F17 VCCO (power), F19 NC, H2 NC, H4 GND (power), H17 GND (power), K4 VCC (power), K18 CLK3/I4 (in), K19 NC, K20 NC, L17 VCC (power), L18 CLK2/IN3 (in), L20 NC, M2 CLK0/IN0 (in), M3 CLK1/IN1 (in), N4 GND (power), N17 GND (power), R4 VCCO (power), R17 VCCO (power), R19 NC, U4 GND (power), U6 VCCO (power), U8 GND (power), U10 VCC (power), U13 GND (power), U15 VCCO (power), U16 NC, U17 GND (power), V10 IN2 (in), V16 TDO (out), W16 NC, W17 NC, Y4 TMS (in), Y10 NC, Y11 NC, Y17 NC, Y18 NC

## CY37256VP256-100BBC
designator U?
Ultra37000 3.3V, ISR High-Performance CPLD
footprint BB256 (BGA, 256-Leads, Body 17x17mm, Pitch 1mm)
3D model CY37256VP256-BB256 (256-Ball Fine Pitch Ball Grid Array 1 mm Pitch (37K & 39K CPLD Devices))
part A pins: A3 I/O26 (io), A4 I/O24 (io), A5 I/O20 (io), A7 I/O11 (io), B2 I/O27 (io), B3 I/O25 (io), B4 I/O23 (io), B5 I/O19 (io), B6 I/O15 (io), B7 I/O10 (io), C1 I/O29 (io), C2 I/O28 (io), C4 I/O22 (io), C5 I/O18 (io), C6 I/O14 (io), C7 I/O9 (io), C8 I/O4 (io), D1 I/O32 (io), D2 I/O31 (io), D3 I/O30 (io), D5 I/O17 (io), D6 I/O13 (io), D7 I/O8 (io), D8 I/O3 (io), E1 I/O35 (io), E2 I/O34 (io), E3 I/O33 (io), E4 I/O21 (io), E5 I/O16 (io), E6 I/O12 (io), E7 I/O7 (io), E8 I/O2 (io), F2 I/O38 (io), F3 I/O37 (io), F4 I/O36 (io), F7 I/O6 (io), F8 I/O1 (io), G1 I/O43 (io), G2 I/O42 (io), G3 I/O41 (io), G4 I/O40 (io), G6 I/O39 (io), G7 I/O5 (io), G8 I/O0 (io), H3 I/O47 (io), H4 I/O46 (io), H6 I/O45 (io), H7 I/O44 (io), J3 I/O51 (io), J4 I/O50 (io), J6 I/O49 (io), J7 I/O48 (io), K1 I/O57 (io), K2 I/O56 (io), K3 I/O55 (io), K4 I/O54 (io), K6 I/O53 (io), K7 I/O52 (io), K8 I/O91 (io), L2 I/O60 (io), L3 I/O59 (io), L4 I/O58 (io), L7 I/O86 (io), L8 I/O92 (io), M1 I/O63 (io), M2 I/O62 (io), M3 I/O61 (io), M4 I/O72 (io), M5 I/O77 (io), M6 I/O82 (io), M8 I/O93 (io), N1 I/O66 (io), N2 I/O65 (io), N3 I/O64 (io), N4 I/O73 (io), N5 I/O78 (io), N6 I/O83 (io), N7 I/O87 (io), N8 I/O94 (io), P1 I/O68 (io), P2 I/O67 (io), P4 I/O74 (io), P5 I/O79 (io), P6 I/O84 (io), P7 I/O88 (io), P8 I/O95 (io), R2 I/O69 (io), R3 I/O70 (io), R4 I/O75 (io), R5 I/O80 (io), R6 I/O85 (io), R7 I/O89 (io), T3 I/O71 (io), T4 I/O76 (io), T5 I/O81 (io), T7 I/O90 (io)
part B pins: A10 I/O186 (io), A12 I/O177 (io), A13 I/O172 (io), A14 I/O167 (io), B10 I/O185 (io), B11 I/O181 (io), B12 I/O176 (io), B13 I/O171 (io), B14 I/O166 (io), B15 I/O165 (io), C9 I/O191 (io), C10 I/O184 (io), C11 I/O180 (io), C12 I/O175 (io), C13 I/O170 (io), C15 I/O163 (io), C16 I/O164 (io), D9 I/O190 (io), D10 I/O183 (io), D11 I/O179 (io), D12 I/O174 (io), D13 I/O169 (io), D14 I/O160 (io), D15 I/O161 (io), D16 I/O162 (io), E9 I/O189 (io), E11 I/O178 (io), E12 I/O173 (io), E13 I/O168 (io), E14 I/O157 (io), E15 I/O158 (io), E16 I/O159 (io), F9 I/O188 (io), F10 I/O182 (io), F13 I/O154 (io), F14 I/O155 (io), F15 I/O156 (io), G9 I/O187 (io), G10 I/O148 (io), G11 I/O149 (io), G13 I/O150 (io), G14 I/O151 (io), G15 I/O152 (io), G16 I/O153 (io), H10 I/O144 (io), H11 I/O145 (io), H13 I/O146 (io), H14 I/O147 (io), J10 I/O140 (io), J11 I/O141 (io), J13 I/O142 (io), J14 I/O143 (io), K9 I/O96 (io), K10 I/O101 (io), K11 I/O135 (io), K13 I/O136 (io), K14 I/O137 (io), K15 I/O138 (io), K16 I/O139 (io), L9 I/O97 (io), L10 I/O102 (io), L13 I/O132 (io), L14 I/O133 (io), L15 I/O134 (io), M9 I/O98 (io), M10 I/O103 (io), M11 I/O108 (io), M12 I/O112 (io), M13 I/O117 (io), M14 I/O129 (io), M15 I/O130 (io), M16 I/O131 (io), N9 I/O99 (io), N10 I/O104 (io), N11 I/O109 (io), N12 I/O113 (io), N14 I/O126 (io), N15 I/O127 (io), N16 I/O128 (io), P9 I/O100 (io), P10 I/O105 (io), P11 I/O110 (io), P12 I/O114 (io), P13 I/O118 (io), P15 I/O124 (io), P16 I/O125 (io), R10 I/O106 (io), R11 I/O111 (io), R12 I/O115 (io), R13 I/O119 (io), R14 I/O121 (io), R15 I/O123 (io), T10 I/O107 (io), T12 I/O116 (io), T13 I/O120 (io), T14 I/O122 (io)
part C pins: A1 GND (power), A2 GND (power), A6 VCC (power), A8 GND (power), A9 GND (power), A11 VCC (power), A15 GND (power), A16 GND (power), B1 GND (power), B8 GND (power), B9 GND (power), B16 GND (power), C3 NC, C14 NC, D4 NC, E10 VCC (power), F1 VCC (power), F5 TCK (in), F6 VCC (power), F11 VCC (power), F12 TDI (in), F16 VCC (power), G5 VCC (power), G12 CLK3/IN4 (in), H1 GND (power), H2 GND (power), H5 CLK0/IN0 (in), H8 GND (power), H9 GND (power), H12 CLK2/IN3 (in), H15 GND (power), H16 GND (power), J1 GND (power), J2 GND (power), J5 NC, J8 GND (power), J9 GND (power), J12 IN2 (in), J15 GND (power), J16 GND (power), K5 CLK1/IN1 (in), K12 VCC (power), L1 VCC (power), L5 TMS (in), L6 VCC (power), L11 VCC (power), L12 TDO (out), L16 VCC (power), M7 VCC (power), N13 NC, P3 NC, P14 NC, R1 GND (power), R8 GND (power), R9 GND (power), R16 GND (power), T1 GND (power), T2 GND (power), T6 VCC (power), T8 GND (power), T9 GND (power), T11 VCC (power), T15 GND (power), T16 GND (power)

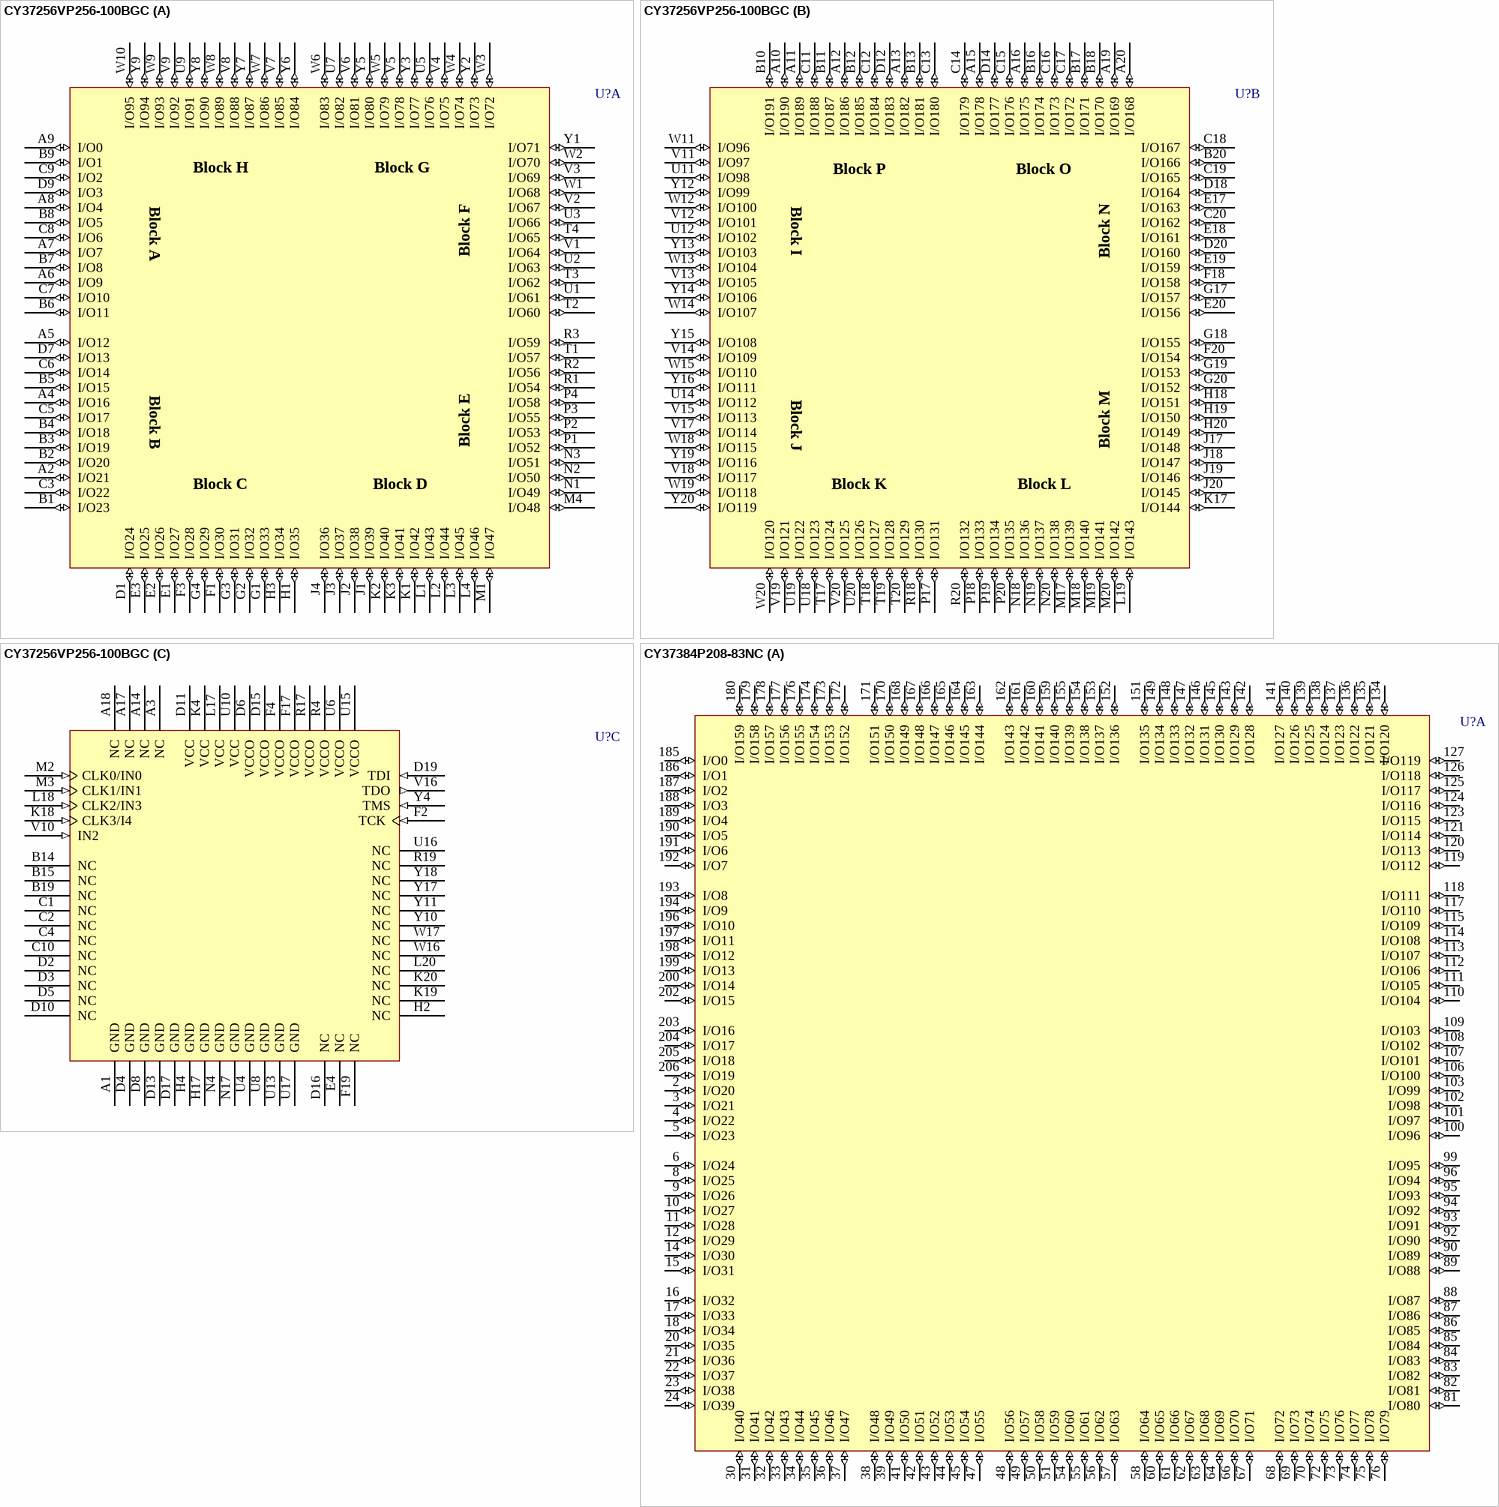
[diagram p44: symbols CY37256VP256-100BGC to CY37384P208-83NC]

## CY37256VP256-100BGC
designator U?
Ultra37000 3.3V, ISR High-Performance CPLD
footprint BG256 (BGA, 292-Leads, Body 27x27mm, Pitch 1.27mm)
3D model CY37256VP256-BG256 (292-Ball Ball Grid Array 1.27 mm Pitch)
part A pins: A2 I/O21 (io), A4 I/O16 (io), A5 I/O12 (io), A6 I/O9 (io), A7 I/O7 (io), A8 I/O4 (io), A9 I/O0 (io), B1 I/O23 (io), B2 I/O20 (io), B3 I/O19 (io), B4 I/O18 (io), B5 I/O15 (io), B6 I/O11 (io), B7 I/O8 (io), B8 I/O5 (io), B9 I/O1 (io), C3 I/O22 (io), C5 I/O17 (io), C6 I/O14 (io), C7 I/O10 (io), C8 I/O6 (io), C9 I/O2 (io), D1 I/O24 (io), D7 I/O13 (io), D9 I/O3 (io), E1 I/O27 (io), E2 I/O26 (io), E3 I/O25 (io), F1 I/O30 (io), F3 I/O28 (io), G1 I/O33 (io), G2 I/O32 (io), G3 I/O31 (io), G4 I/O29 (io), H1 I/O35 (io), H3 I/O34 (io), J1 I/O39 (io), J2 I/O38 (io), J3 I/O37 (io), J4 I/O36 (io), K1 I/O42 (io), K2 I/O40 (io), K3 I/O41 (io), L1 I/O43 (io), L2 I/O44 (io), L3 I/O45 (io), L4 I/O46 (io), M1 I/O47 (io), M4 I/O48 (io), N1 I/O49 (io), N2 I/O50 (io), N3 I/O51 (io), P1 I/O52 (io), P2 I/O53 (io), P3 I/O55 (io), P4 I/O58 (io), R1 I/O54 (io), R2 I/O56 (io), R3 I/O59 (io), T1 I/O57 (io), T2 I/O60 (io), T3 I/O62 (io), T4 I/O65 (io), U1 I/O61 (io), U2 I/O63 (io), U3 I/O66 (io), U5 I/O76 (io), U7 I/O82 (io), U9 I/O91 (io), V1 I/O64 (io), V2 I/O67 (io), V3 I/O69 (io), V4 I/O75 (io), V5 I/O78 (io), V6 I/O81 (io), V7 I/O85 (io), V8 I/O88 (io), V9 I/O92 (io), W1 I/O68 (io), W2 I/O70 (io), W3 I/O72 (io), W4 I/O74 (io), W5 I/O79 (io), W6 I/O83 (io), W7 I/O86 (io), W8 I/O89 (io), W9 I/O93 (io), W10 I/O95 (io), Y1 I/O71 (io), Y2 I/O73 (io), Y3 I/O77 (io), Y5 I/O80 (io), Y6 I/O84 (io), Y7 I/O87 (io), Y8 I/O90 (io), Y9 I/O94 (io)
part B pins: A10 I/O190 (io), A11 I/O189 (io), A12 I/O186 (io), A13 I/O182 (io), A15 I/O178 (io), A16 I/O175 (io), A19 I/O169 (io), A20 I/O168 (io), B10 I/O191 (io), B11 I/O187 (io), B12 I/O185 (io), B13 I/O181 (io), B16 I/O174 (io), B17 I/O171 (io), B18 I/O170 (io), B20 I/O166 (io), C11 I/O188 (io), C12 I/O184 (io), C13 I/O180 (io), C14 I/O179 (io), C15 I/O176 (io), C16 I/O173 (io), C17 I/O172 (io), C18 I/O167 (io), C19 I/O165 (io), C20 I/O162 (io), D12 I/O183 (io), D14 I/O177 (io), D18 I/O164 (io), D20 I/O160 (io), E17 I/O163 (io), E18 I/O161 (io), E19 I/O159 (io), E20 I/O156 (io), F18 I/O158 (io), F20 I/O154 (io), G17 I/O157 (io), G18 I/O155 (io), G19 I/O153 (io), G20 I/O152 (io), H18 I/O151 (io), H19 I/O150 (io), H20 I/O149 (io), J17 I/O148 (io), J18 I/O147 (io), J19 I/O146 (io), J20 I/O145 (io), K17 I/O144 (io), L19 I/O143 (io), M17 I/O139 (io), M18 I/O140 (io), M19 I/O141 (io), M20 I/O142 (io), N18 I/O136 (io), N19 I/O137 (io), N20 I/O138 (io), P17 I/O131 (io), P18 I/O133 (io), P19 I/O134 (io), P20 I/O135 (io), R18 I/O130 (io), R20 I/O132 (io), T17 I/O124 (io), T18 I/O127 (io), T19 I/O128 (io), T20 I/O129 (io), U11 I/O98 (io), U12 I/O102 (io), U14 I/O112 (io), U18 I/O123 (io), U19 I/O122 (io), U20 I/O126 (io), V11 I/O97 (io), V12 I/O101 (io), V13 I/O105 (io), V14 I/O109 (io), V15 I/O113 (io), V17 I/O114 (io), V18 I/O117 (io), V19 I/O121 (io), V20 I/O125 (io), W11 I/O96 (io), W12 I/O100 (io), W13 I/O104 (io), W14 I/O107 (io), W15 I/O110 (io), W18 I/O115 (io), W19 I/O118 (io), W20 I/O120 (io), Y12 I/O99 (io), Y13 I/O103 (io), Y14 I/O106 (io), Y15 I/O108 (io), Y16 I/O111 (io), Y19 I/O116 (io), Y20 I/O119 (io)
part C pins: A1 GND (power), A3 NC, A14 NC, A17 NC, A18 NC, B14 NC, B15 NC, B19 NC, C1 NC, C2 NC, C4 NC, C10 NC, D2 NC, D3 NC, D4 GND (power), D5 NC, D6 VCCO (power), D8 GND (power), D10 NC, D11 VCC (power), D13 GND (power), D15 VCCO (power), D16 NC, D17 GND (power), D19 TDI (in), E4 NC, F2 TCK (in), F4 VCCO (power), F17 VCCO (power), F19 NC, H2 NC, H4 GND (power), H17 GND (power), K4 VCC (power), K18 CLK3/I4 (in), K19 NC, K20 NC, L17 VCC (power), L18 CLK2/IN3 (in), L20 NC, M2 CLK0/IN0 (in), M3 CLK1/IN1 (in), N4 GND (power), N17 GND (power), R4 VCCO (power), R17 VCCO (power), R19 NC, U4 GND (power), U6 VCCO (power), U8 GND (power), U10 VCC (power), U13 GND (power), U15 VCCO (power), U16 NC, U17 GND (power), V10 IN2 (in), V16 TDO (out), W16 NC, W17 NC, Y4 TMS (in), Y10 NC, Y11 NC, Y17 NC, Y18 NC

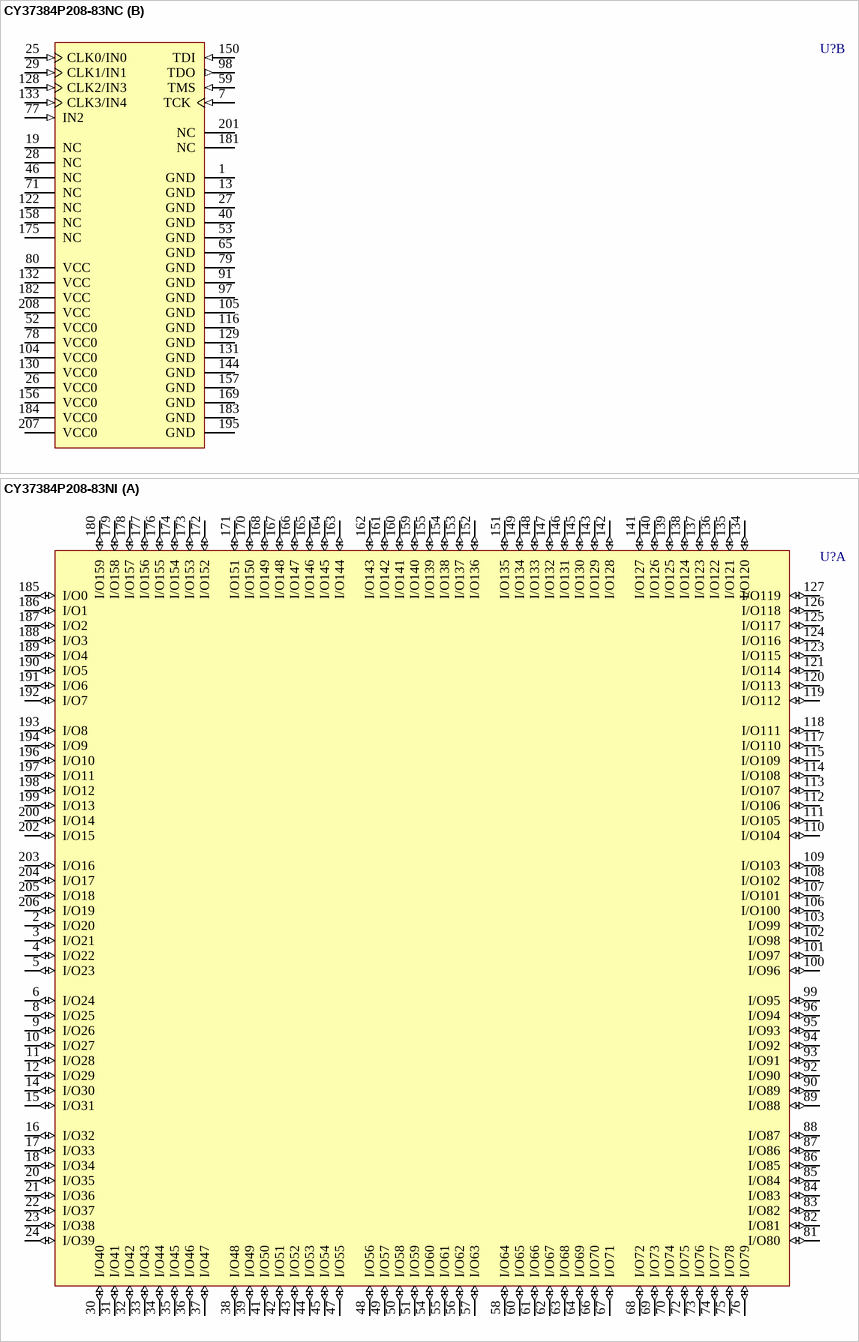
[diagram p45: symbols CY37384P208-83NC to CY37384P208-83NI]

## CY37384P208-83NC
designator U?
Ultra37000 5V, ISR High-Performance CPLD
footprint N208_N (Shrink QFP, 208-Leads, Body 28x28mm, Pitch 0.5mm, IPC Medium Density)
footprint N208_L (Shrink QFP, 208-Leads, Body 28x28mm, Pitch 0.5mm, IPC High Density)
footprint N208_M (Shrink QFP, 208-Leads, Body 28x28mm, Pitch 0.5mm, IPC Low Density)
3D model CY37384P208-N208 (208-Pin Plastic Shrink Quad Flat Pack 0.5 mm Pitch)
part A pins: 2 I/O20 (io), 3 I/O21 (io), 4 I/O22 (io), 5 I/O23 (io), 6 I/O24 (io), 8 I/O25 (io), 9 I/O26 (io), 10 I/O27 (io), 11 I/O28 (io), 12 I/O29 (io), 14 I/O30 (io), 15 I/O31 (io), 16 I/O32 (io), 17 I/O33 (io), 18 I/O34 (io), 20 I/O35 (io), 21 I/O36 (io), 22 I/O37 (io), 23 I/O38 (io), 24 I/O39 (io), 30 I/O40 (io), 31 I/O41 (io), 32 I/O42 (io), 33 I/O43 (io), 34 I/O44 (io), 35 I/O45 (io), 36 I/O46 (io), 37 I/O47 (io), 38 I/O48 (io), 39 I/O49 (io), 41 I/O50 (io), 42 I/O51 (io), 43 I/O52 (io), 44 I/O53 (io), 45 I/O54 (io), 47 I/O55 (io), 48 I/O56 (io), 49 I/O57 (io), 50 I/O58 (io), 51 I/O59 (io), 54 I/O60 (io), 55 I/O61 (io), 56 I/O62 (io), 57 I/O63 (io), 58 I/O64 (io), 60 I/O65 (io), 61 I/O66 (io), 62 I/O67 (io), 63 I/O68 (io), 64 I/O69 (io), 66 I/O70 (io), 67 I/O71 (io), 68 I/O72 (io), 69 I/O73 (io), 70 I/O74 (io), 72 I/O75 (io), 73 I/O76 (io), 74 I/O77 (io), 75 I/O78 (io), 76 I/O79 (io), 81 I/O80 (io), 82 I/O81 (io), 83 I/O82 (io), 84 I/O83 (io), 85 I/O84 (io), 86 I/O85 (io), 87 I/O86 (io), 88 I/O87 (io), 89 I/O88 (io), 90 I/O89 (io), 92 I/O90 (io), 93 I/O91 (io), 94 I/O92 (io), 95 I/O93 (io), 96 I/O94 (io), 99 I/O95 (io), 100 I/O96 (io), 101 I/O97 (io), 102 I/O98 (io), 103 I/O99 (io), 106 I/O100 (io), 107 I/O101 (io), 108 I/O102 (io), 109 I/O103 (io), 110 I/O104 (io), 111 I/O105 (io), 112 I/O106 (io), 113 I/O107 (io), 114 I/O108 (io), 115 I/O109 (io), 117 I/O110 (io), 118 I/O111 (io), 119 I/O112 (io), 120 I/O113 (io), 121 I/O114 (io), 123 I/O115 (io), 124 I/O116 (io), 125 I/O117 (io), 126 I/O118 (io), 127 I/O119 (io), 134 I/O120 (io), 135 I/O121 (io), 136 I/O122 (io), 137 I/O123 (io), 138 I/O124 (io), 139 I/O125 (io), 140 I/O126 (io), 141 I/O127 (io), 142 I/O128 (io), 143 I/O129 (io), 145 I/O130 (io), 146 I/O131 (io), 147 I/O132 (io), 148 I/O133 (io), 149 I/O134 (io), 151 I/O135 (io), 152 I/O136 (io), 153 I/O137 (io), 154 I/O138 (io), 155 I/O139 (io), 159 I/O140 (io), 160 I/O141 (io), 161 I/O142 (io), 162 I/O143 (io), 163 I/O144 (io), 164 I/O145 (io), 165 I/O146 (io), 166 I/O147 (io), 167 I/O148 (io), 168 I/O149 (io), 170 I/O150 (io), 171 I/O151 (io), 172 I/O152 (io), 173 I/O153 (io), 174 I/O154 (io), 176 I/O155 (io), 177 I/O156 (io), 178 I/O157 (io), 179 I/O158 (io), 180 I/O159 (io), 185 I/O0 (io), 186 I/O1 (io), 187 I/O2 (io), 188 I/O3 (io), 189 I/O4 (io), 190 I/O5 (io), 191 I/O6 (io), 192 I/O7 (io), 193 I/O8 (io), 194 I/O9 (io), 196 I/O10 (io), 197 I/O11 (io), 198 I/O12 (io), 199 I/O13 (io), 200 I/O14 (io), 202 I/O15 (io), 203 I/O16 (io), 204 I/O17 (io), 205 I/O18 (io), 206 I/O19 (io)
part B pins: 1 GND (power), 7 TCK (in), 13 GND (power), 19 NC, 25 CLK0/IN0 (in), 26 VCC0 (power), 27 GND (power), 28 NC, 29 CLK1/IN1 (in), 40 GND (power), 46 NC, 52 VCC0 (power), 53 GND (power), 59 TMS (in), 65 GND (power), 71 NC, 77 IN2 (in), 78 VCC0 (power), 79 GND (power), 80 VCC (power), 91 GND (power), 97 GND (power), 98 TDO (out), 104 VCC0 (power), 105 GND (power), 116 GND (power), 122 NC, 128 CLK2/IN3 (in), 129 GND (power), 130 VCC0 (power), 131 GND (power), 132 VCC (power), 133 CLK3/IN4 (in), 144 GND (power), 150 TDI (in), 156 VCC0 (power), 157 GND (power), 158 NC, 169 GND (power), 175 NC, 181 NC, 182 VCC (power), 183 GND (power), 184 VCC0 (power), 195 GND (power), 201 NC, 207 VCC0 (power), 208 VCC (power)

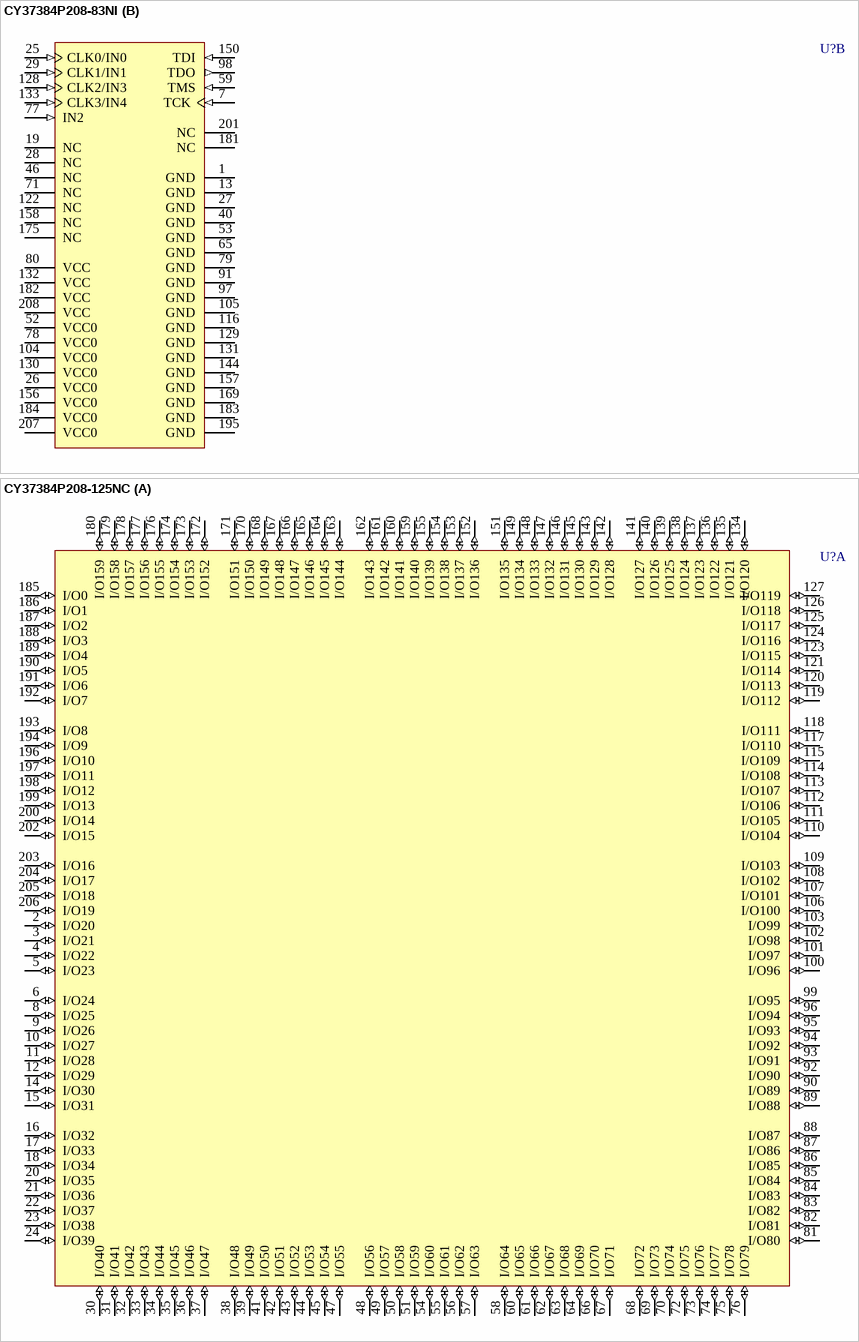
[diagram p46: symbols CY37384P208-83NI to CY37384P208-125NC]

## CY37384P208-83NI
designator U?
Ultra37000 5V, ISR High-Performance CPLD
footprint N208_N (Shrink QFP, 208-Leads, Body 28x28mm, Pitch 0.5mm, IPC Medium Density)
footprint N208_L (Shrink QFP, 208-Leads, Body 28x28mm, Pitch 0.5mm, IPC High Density)
footprint N208_M (Shrink QFP, 208-Leads, Body 28x28mm, Pitch 0.5mm, IPC Low Density)
3D model CY37384P208-N208 (208-Pin Plastic Shrink Quad Flat Pack 0.5 mm Pitch)
part A pins: 2 I/O20 (io), 3 I/O21 (io), 4 I/O22 (io), 5 I/O23 (io), 6 I/O24 (io), 8 I/O25 (io), 9 I/O26 (io), 10 I/O27 (io), 11 I/O28 (io), 12 I/O29 (io), 14 I/O30 (io), 15 I/O31 (io), 16 I/O32 (io), 17 I/O33 (io), 18 I/O34 (io), 20 I/O35 (io), 21 I/O36 (io), 22 I/O37 (io), 23 I/O38 (io), 24 I/O39 (io), 30 I/O40 (io), 31 I/O41 (io), 32 I/O42 (io), 33 I/O43 (io), 34 I/O44 (io), 35 I/O45 (io), 36 I/O46 (io), 37 I/O47 (io), 38 I/O48 (io), 39 I/O49 (io), 41 I/O50 (io), 42 I/O51 (io), 43 I/O52 (io), 44 I/O53 (io), 45 I/O54 (io), 47 I/O55 (io), 48 I/O56 (io), 49 I/O57 (io), 50 I/O58 (io), 51 I/O59 (io), 54 I/O60 (io), 55 I/O61 (io), 56 I/O62 (io), 57 I/O63 (io), 58 I/O64 (io), 60 I/O65 (io), 61 I/O66 (io), 62 I/O67 (io), 63 I/O68 (io), 64 I/O69 (io), 66 I/O70 (io), 67 I/O71 (io), 68 I/O72 (io), 69 I/O73 (io), 70 I/O74 (io), 72 I/O75 (io), 73 I/O76 (io), 74 I/O77 (io), 75 I/O78 (io), 76 I/O79 (io), 81 I/O80 (io), 82 I/O81 (io), 83 I/O82 (io), 84 I/O83 (io), 85 I/O84 (io), 86 I/O85 (io), 87 I/O86 (io), 88 I/O87 (io), 89 I/O88 (io), 90 I/O89 (io), 92 I/O90 (io), 93 I/O91 (io), 94 I/O92 (io), 95 I/O93 (io), 96 I/O94 (io), 99 I/O95 (io), 100 I/O96 (io), 101 I/O97 (io), 102 I/O98 (io), 103 I/O99 (io), 106 I/O100 (io), 107 I/O101 (io), 108 I/O102 (io), 109 I/O103 (io), 110 I/O104 (io), 111 I/O105 (io), 112 I/O106 (io), 113 I/O107 (io), 114 I/O108 (io), 115 I/O109 (io), 117 I/O110 (io), 118 I/O111 (io), 119 I/O112 (io), 120 I/O113 (io), 121 I/O114 (io), 123 I/O115 (io), 124 I/O116 (io), 125 I/O117 (io), 126 I/O118 (io), 127 I/O119 (io), 134 I/O120 (io), 135 I/O121 (io), 136 I/O122 (io), 137 I/O123 (io), 138 I/O124 (io), 139 I/O125 (io), 140 I/O126 (io), 141 I/O127 (io), 142 I/O128 (io), 143 I/O129 (io), 145 I/O130 (io), 146 I/O131 (io), 147 I/O132 (io), 148 I/O133 (io), 149 I/O134 (io), 151 I/O135 (io), 152 I/O136 (io), 153 I/O137 (io), 154 I/O138 (io), 155 I/O139 (io), 159 I/O140 (io), 160 I/O141 (io), 161 I/O142 (io), 162 I/O143 (io), 163 I/O144 (io), 164 I/O145 (io), 165 I/O146 (io), 166 I/O147 (io), 167 I/O148 (io), 168 I/O149 (io), 170 I/O150 (io), 171 I/O151 (io), 172 I/O152 (io), 173 I/O153 (io), 174 I/O154 (io), 176 I/O155 (io), 177 I/O156 (io), 178 I/O157 (io), 179 I/O158 (io), 180 I/O159 (io), 185 I/O0 (io), 186 I/O1 (io), 187 I/O2 (io), 188 I/O3 (io), 189 I/O4 (io), 190 I/O5 (io), 191 I/O6 (io), 192 I/O7 (io), 193 I/O8 (io), 194 I/O9 (io), 196 I/O10 (io), 197 I/O11 (io), 198 I/O12 (io), 199 I/O13 (io), 200 I/O14 (io), 202 I/O15 (io), 203 I/O16 (io), 204 I/O17 (io), 205 I/O18 (io), 206 I/O19 (io)
part B pins: 1 GND (power), 7 TCK (in), 13 GND (power), 19 NC, 25 CLK0/IN0 (in), 26 VCC0 (power), 27 GND (power), 28 NC, 29 CLK1/IN1 (in), 40 GND (power), 46 NC, 52 VCC0 (power), 53 GND (power), 59 TMS (in), 65 GND (power), 71 NC, 77 IN2 (in), 78 VCC0 (power), 79 GND (power), 80 VCC (power), 91 GND (power), 97 GND (power), 98 TDO (out), 104 VCC0 (power), 105 GND (power), 116 GND (power), 122 NC, 128 CLK2/IN3 (in), 129 GND (power), 130 VCC0 (power), 131 GND (power), 132 VCC (power), 133 CLK3/IN4 (in), 144 GND (power), 150 TDI (in), 156 VCC0 (power), 157 GND (power), 158 NC, 169 GND (power), 175 NC, 181 NC, 182 VCC (power), 183 GND (power), 184 VCC0 (power), 195 GND (power), 201 NC, 207 VCC0 (power), 208 VCC (power)

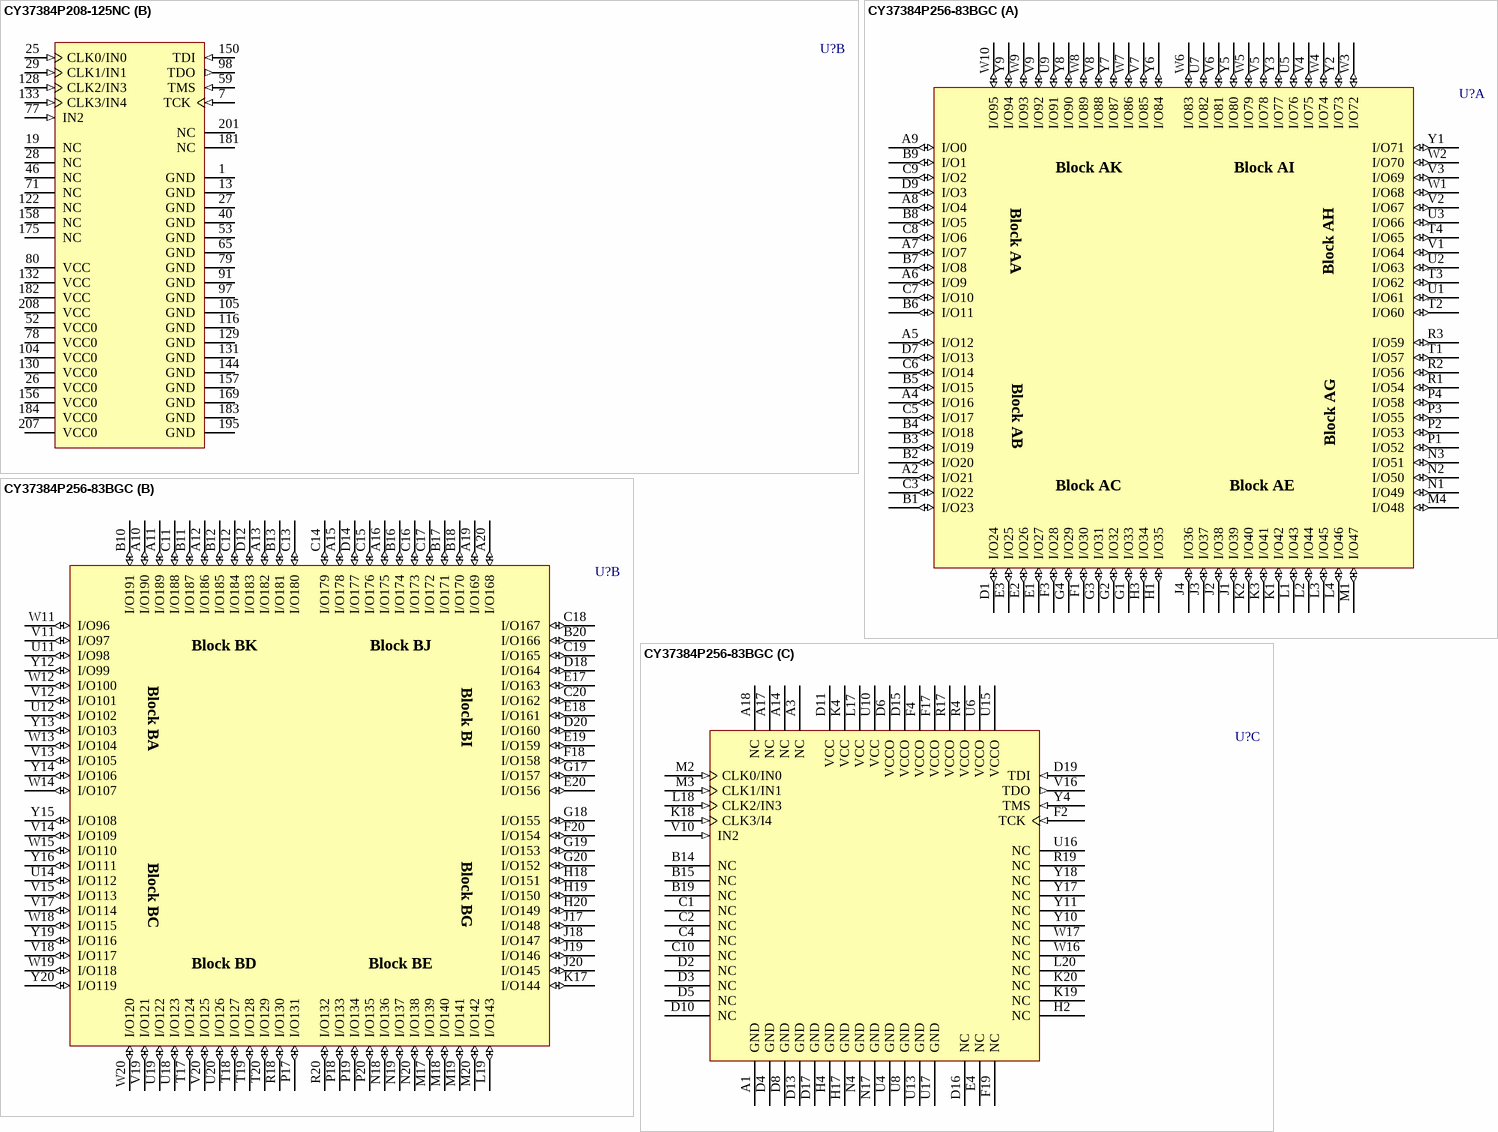
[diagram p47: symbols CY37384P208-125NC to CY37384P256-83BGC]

## CY37384P208-125NC
designator U?
Ultra37000 5V, ISR High-Performance CPLD
footprint N208_N (Shrink QFP, 208-Leads, Body 28x28mm, Pitch 0.5mm, IPC Medium Density)
footprint N208_L (Shrink QFP, 208-Leads, Body 28x28mm, Pitch 0.5mm, IPC High Density)
footprint N208_M (Shrink QFP, 208-Leads, Body 28x28mm, Pitch 0.5mm, IPC Low Density)
3D model CY37384P208-N208 (208-Pin Plastic Shrink Quad Flat Pack 0.5 mm Pitch)
part A pins: 2 I/O20 (io), 3 I/O21 (io), 4 I/O22 (io), 5 I/O23 (io), 6 I/O24 (io), 8 I/O25 (io), 9 I/O26 (io), 10 I/O27 (io), 11 I/O28 (io), 12 I/O29 (io), 14 I/O30 (io), 15 I/O31 (io), 16 I/O32 (io), 17 I/O33 (io), 18 I/O34 (io), 20 I/O35 (io), 21 I/O36 (io), 22 I/O37 (io), 23 I/O38 (io), 24 I/O39 (io), 30 I/O40 (io), 31 I/O41 (io), 32 I/O42 (io), 33 I/O43 (io), 34 I/O44 (io), 35 I/O45 (io), 36 I/O46 (io), 37 I/O47 (io), 38 I/O48 (io), 39 I/O49 (io), 41 I/O50 (io), 42 I/O51 (io), 43 I/O52 (io), 44 I/O53 (io), 45 I/O54 (io), 47 I/O55 (io), 48 I/O56 (io), 49 I/O57 (io), 50 I/O58 (io), 51 I/O59 (io), 54 I/O60 (io), 55 I/O61 (io), 56 I/O62 (io), 57 I/O63 (io), 58 I/O64 (io), 60 I/O65 (io), 61 I/O66 (io), 62 I/O67 (io), 63 I/O68 (io), 64 I/O69 (io), 66 I/O70 (io), 67 I/O71 (io), 68 I/O72 (io), 69 I/O73 (io), 70 I/O74 (io), 72 I/O75 (io), 73 I/O76 (io), 74 I/O77 (io), 75 I/O78 (io), 76 I/O79 (io), 81 I/O80 (io), 82 I/O81 (io), 83 I/O82 (io), 84 I/O83 (io), 85 I/O84 (io), 86 I/O85 (io), 87 I/O86 (io), 88 I/O87 (io), 89 I/O88 (io), 90 I/O89 (io), 92 I/O90 (io), 93 I/O91 (io), 94 I/O92 (io), 95 I/O93 (io), 96 I/O94 (io), 99 I/O95 (io), 100 I/O96 (io), 101 I/O97 (io), 102 I/O98 (io), 103 I/O99 (io), 106 I/O100 (io), 107 I/O101 (io), 108 I/O102 (io), 109 I/O103 (io), 110 I/O104 (io), 111 I/O105 (io), 112 I/O106 (io), 113 I/O107 (io), 114 I/O108 (io), 115 I/O109 (io), 117 I/O110 (io), 118 I/O111 (io), 119 I/O112 (io), 120 I/O113 (io), 121 I/O114 (io), 123 I/O115 (io), 124 I/O116 (io), 125 I/O117 (io), 126 I/O118 (io), 127 I/O119 (io), 134 I/O120 (io), 135 I/O121 (io), 136 I/O122 (io), 137 I/O123 (io), 138 I/O124 (io), 139 I/O125 (io), 140 I/O126 (io), 141 I/O127 (io), 142 I/O128 (io), 143 I/O129 (io), 145 I/O130 (io), 146 I/O131 (io), 147 I/O132 (io), 148 I/O133 (io), 149 I/O134 (io), 151 I/O135 (io), 152 I/O136 (io), 153 I/O137 (io), 154 I/O138 (io), 155 I/O139 (io), 159 I/O140 (io), 160 I/O141 (io), 161 I/O142 (io), 162 I/O143 (io), 163 I/O144 (io), 164 I/O145 (io), 165 I/O146 (io), 166 I/O147 (io), 167 I/O148 (io), 168 I/O149 (io), 170 I/O150 (io), 171 I/O151 (io), 172 I/O152 (io), 173 I/O153 (io), 174 I/O154 (io), 176 I/O155 (io), 177 I/O156 (io), 178 I/O157 (io), 179 I/O158 (io), 180 I/O159 (io), 185 I/O0 (io), 186 I/O1 (io), 187 I/O2 (io), 188 I/O3 (io), 189 I/O4 (io), 190 I/O5 (io), 191 I/O6 (io), 192 I/O7 (io), 193 I/O8 (io), 194 I/O9 (io), 196 I/O10 (io), 197 I/O11 (io), 198 I/O12 (io), 199 I/O13 (io), 200 I/O14 (io), 202 I/O15 (io), 203 I/O16 (io), 204 I/O17 (io), 205 I/O18 (io), 206 I/O19 (io)
part B pins: 1 GND (power), 7 TCK (in), 13 GND (power), 19 NC, 25 CLK0/IN0 (in), 26 VCC0 (power), 27 GND (power), 28 NC, 29 CLK1/IN1 (in), 40 GND (power), 46 NC, 52 VCC0 (power), 53 GND (power), 59 TMS (in), 65 GND (power), 71 NC, 77 IN2 (in), 78 VCC0 (power), 79 GND (power), 80 VCC (power), 91 GND (power), 97 GND (power), 98 TDO (out), 104 VCC0 (power), 105 GND (power), 116 GND (power), 122 NC, 128 CLK2/IN3 (in), 129 GND (power), 130 VCC0 (power), 131 GND (power), 132 VCC (power), 133 CLK3/IN4 (in), 144 GND (power), 150 TDI (in), 156 VCC0 (power), 157 GND (power), 158 NC, 169 GND (power), 175 NC, 181 NC, 182 VCC (power), 183 GND (power), 184 VCC0 (power), 195 GND (power), 201 NC, 207 VCC0 (power), 208 VCC (power)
